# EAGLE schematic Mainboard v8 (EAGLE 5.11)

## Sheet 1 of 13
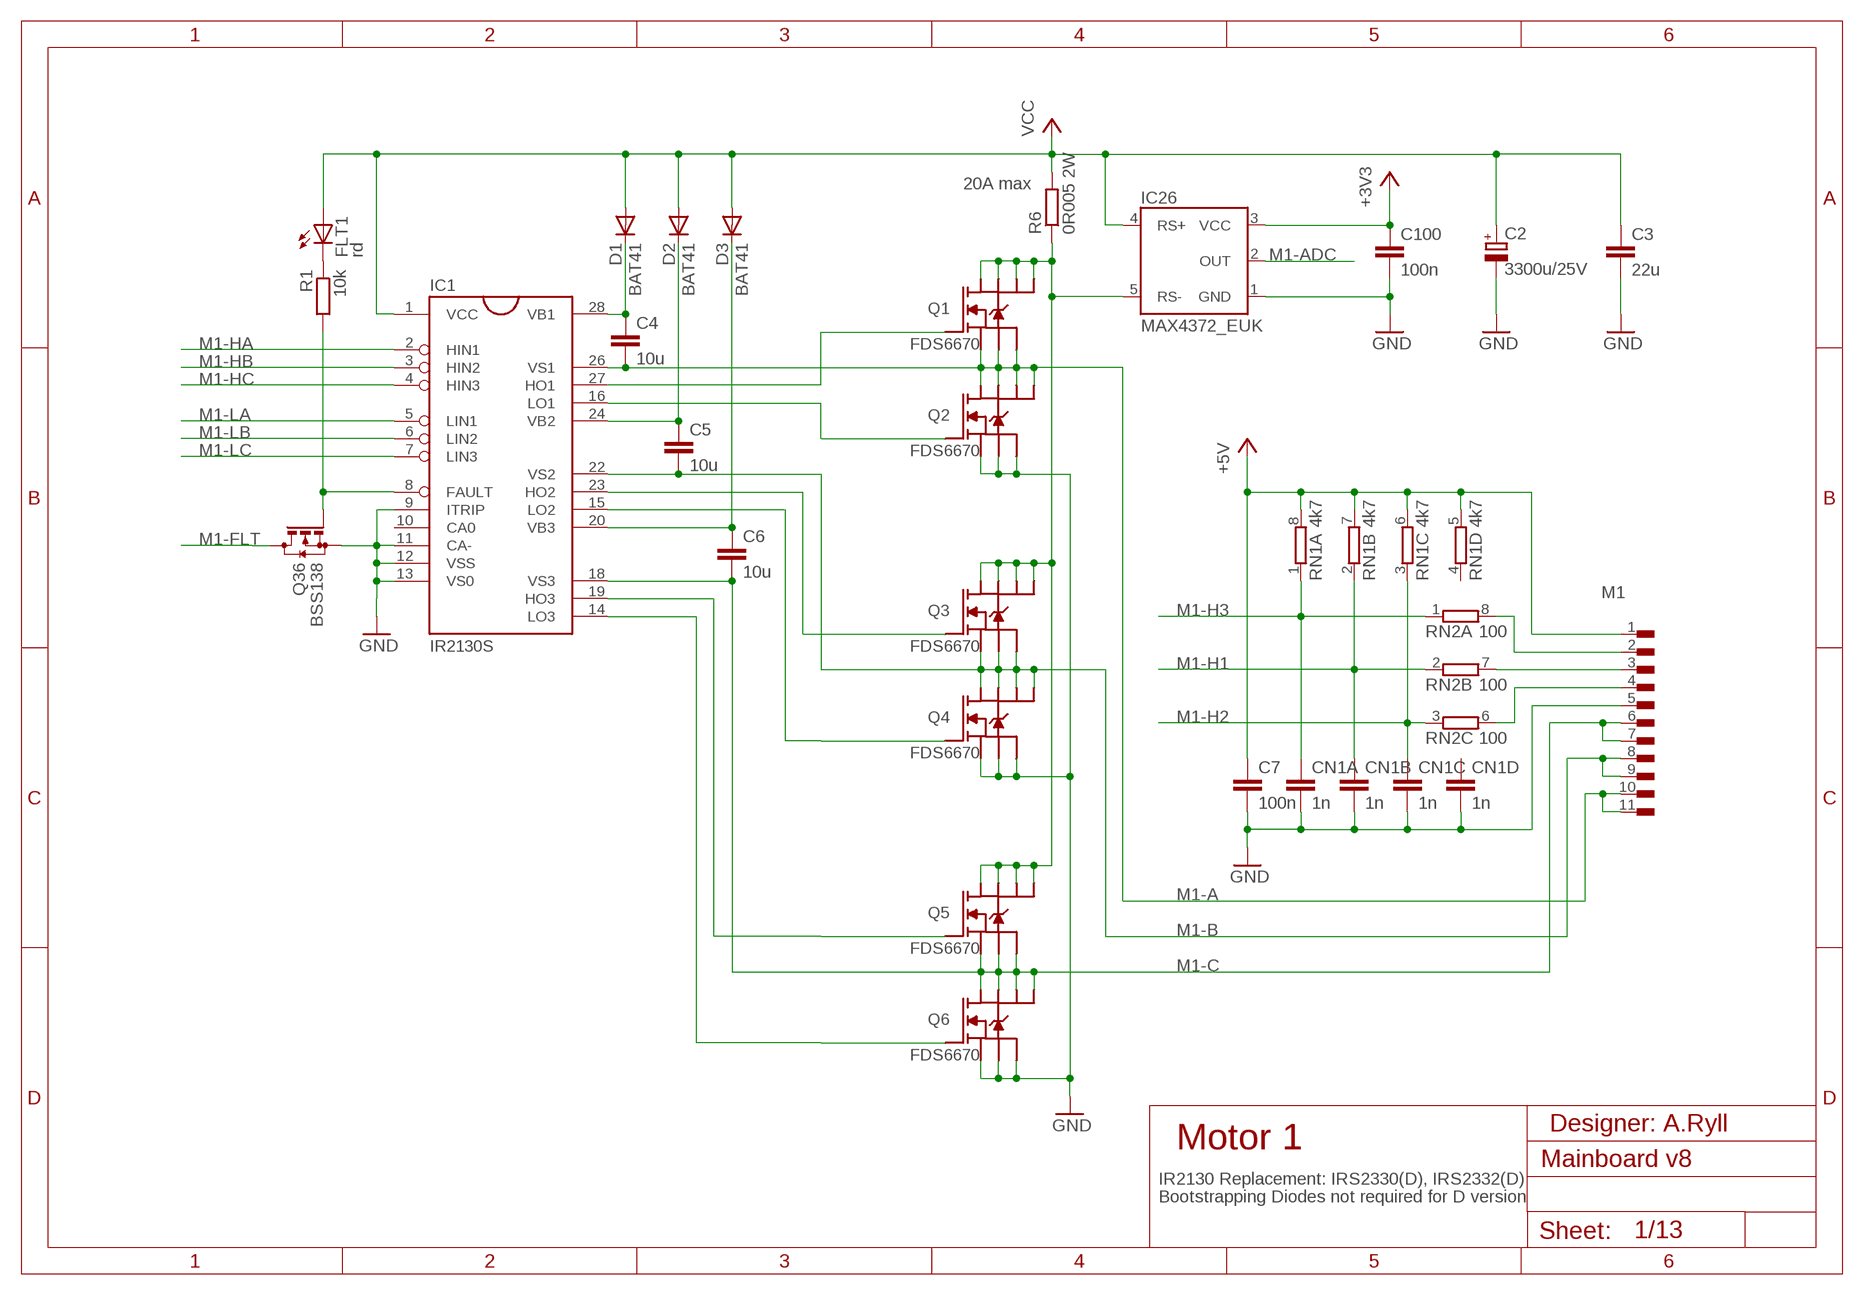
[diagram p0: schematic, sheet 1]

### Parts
C2  3300u/25V  CPOL-EU  [C25-16L]
C3  22u  C-EUC1206  [C1206]
C4  10u  C-EUC0805  [C0805]
C5  10u  C-EUC0805  [C0805]
C6  10u  C-EUC0805  [C0805]
C7  100n  C-EUC0805  [C0805]
C100  100n  C-EUC0805  [C0805]
CN1  1n  4C-NCAY16  [CAY16]
D1  BAT41  DIODE-SOD323-W  [SOD323-W]
D2  BAT41  DIODE-SOD323-W  [SOD323-W]
D3  BAT41  DIODE-SOD323-W  [SOD323-W]
FLT1  rd  LEDCHIP-LED0805  [CHIP-LED0805]
IC1  IR2130S  [SO28W]
IC26  MAX4372_EUK  [SOT23-5]
M1  MOLEX11  [MOLEX11]
Q1  FDS6670  NMOS4D  [SOIC8]
Q2  FDS6670  NMOS4D  [SOIC8]
Q3  FDS6670  NMOS4D  [SOIC8]
Q4  FDS6670  NMOS4D  [SOIC8]
Q5  FDS6670  NMOS4D  [SOIC8]
Q6  FDS6670  NMOS4D  [SOIC8]
Q36  BSS138  BSS123  [SOT23]
R1  10k  R-EU_R0805  [R0805]
R6  0R005 2W  R-EU_R2512  [R2512]
RN1  4k7  4R-NCAY16  [CAY16]
RN2  100  4R-NCAY16  [CAY16]

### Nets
+3V3: C100.1 IC26.3(VCC) ; also sheet 2,3,4,5,6,7,8,9,11,12,13
+5V: C7.1 M1.1(-1) RN1.5 RN1.6 RN1.7 RN1.8 ; also sheet 2,3,4,5,7,8,10,11
FLT1: IC1.8(FAULT) Q36.1(G) R1.2
GND: C2.B(-) C3.2 C7.2 C100.2 CN1.5 CN1.6 CN1.7 CN1.8 IC1.9(ITRIP) IC1.11(CA-) IC1.12(VSS) IC1.13(VS0) IC26.1(GND) M1.5(-5) Q2.1(S1) Q2.2(S2) Q2.3(S3) Q4.1(S1) Q4.2(S2) Q4.3(S3) Q6.1(S1) Q6.2(S2) Q6.3(S3) Q36.2(S) ; also sheet 2,3,4,5,6,7,8,9,10,11,12,13
M1-A: C4.2 IC1.26(VS1) M1.10(-10) M1.11(-11) Q1.1(S1) Q1.2(S2) Q1.3(S3) Q2.5(D1) Q2.6(D2) Q2.7(D3) Q2.8(D4)
M1-ADC: IC26.2(OUT) ; also sheet 6
M1-B: C5.2 IC1.22(VS2) M1.8(-8) M1.9(-9) Q3.1(S1) Q3.2(S2) Q3.3(S3) Q4.5(D1) Q4.6(D2) Q4.7(D3) Q4.8(D4)
M1-C: C6.2 IC1.18(VS3) M1.6(-6) M1.7(-7) Q5.1(S1) Q5.2(S2) Q5.3(S3) Q6.5(D1) Q6.6(D2) Q6.7(D3) Q6.8(D4)
M1-FLT: Q36.3(D) ; also sheet 6
M1-H1: CN1.2 RN1.2 RN2.2 ; also sheet 7,9
M1-H2: CN1.3 RN1.3 RN2.3 ; also sheet 7,9
M1-H3: CN1.1 RN1.1 RN2.1 ; also sheet 7,9
M1-HA: IC1.2(HIN1) ; also sheet 9
M1-HB: IC1.3(HIN2) ; also sheet 9
M1-HC: IC1.4(HIN3) ; also sheet 9
M1-LA: IC1.5(LIN1) ; also sheet 9
M1-LB: IC1.6(LIN2) ; also sheet 9
M1-LC: IC1.7(LIN3) ; also sheet 9
M1-PWR: IC26.5(RS-) Q1.5(D1) Q1.6(D2) Q1.7(D3) Q1.8(D4) Q3.5(D1) Q3.6(D2) Q3.7(D3) Q3.8(D4) Q5.5(D1) Q5.6(D2) Q5.7(D3) Q5.8(D4) R6.1
N$2: IC1.27(HO1) Q1.4(G)
N$4: IC1.16(LO1) Q2.4(G)
N$5: IC1.23(HO2) Q3.4(G)
N$8: M1.2(-2) RN2.8
N$9: M1.3(-3) RN2.7
N$10: M1.4(-4) RN2.6
N$12: IC1.15(LO2) Q4.4(G)
N$16: IC1.19(HO3) Q5.4(G)
N$18: IC1.14(LO3) Q6.4(G)
N$33: C4.1 D1.C IC1.28(VB1)
N$35: C5.1 D2.C IC1.24(VB2)
N$37: C6.1 D3.C IC1.20(VB3)
N$51: FLT1.C R1.1
VCC: C2.A(+) C3.1 D1.A D2.A D3.A FLT1.A IC1.1(VCC) IC26.4(RS+) R6.2 ; also sheet 2,3,4,5,8,10
Unconnected: CN1.4 IC1.10(CA0) RN1.4 RN2.4 RN2.5

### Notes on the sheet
- 20A max
- Designer: A.Ryll
- Motor 1
- IR2130 Replacement: IRS2330(D), IRS2332(D)
- Bootstrapping Diodes not required for D version

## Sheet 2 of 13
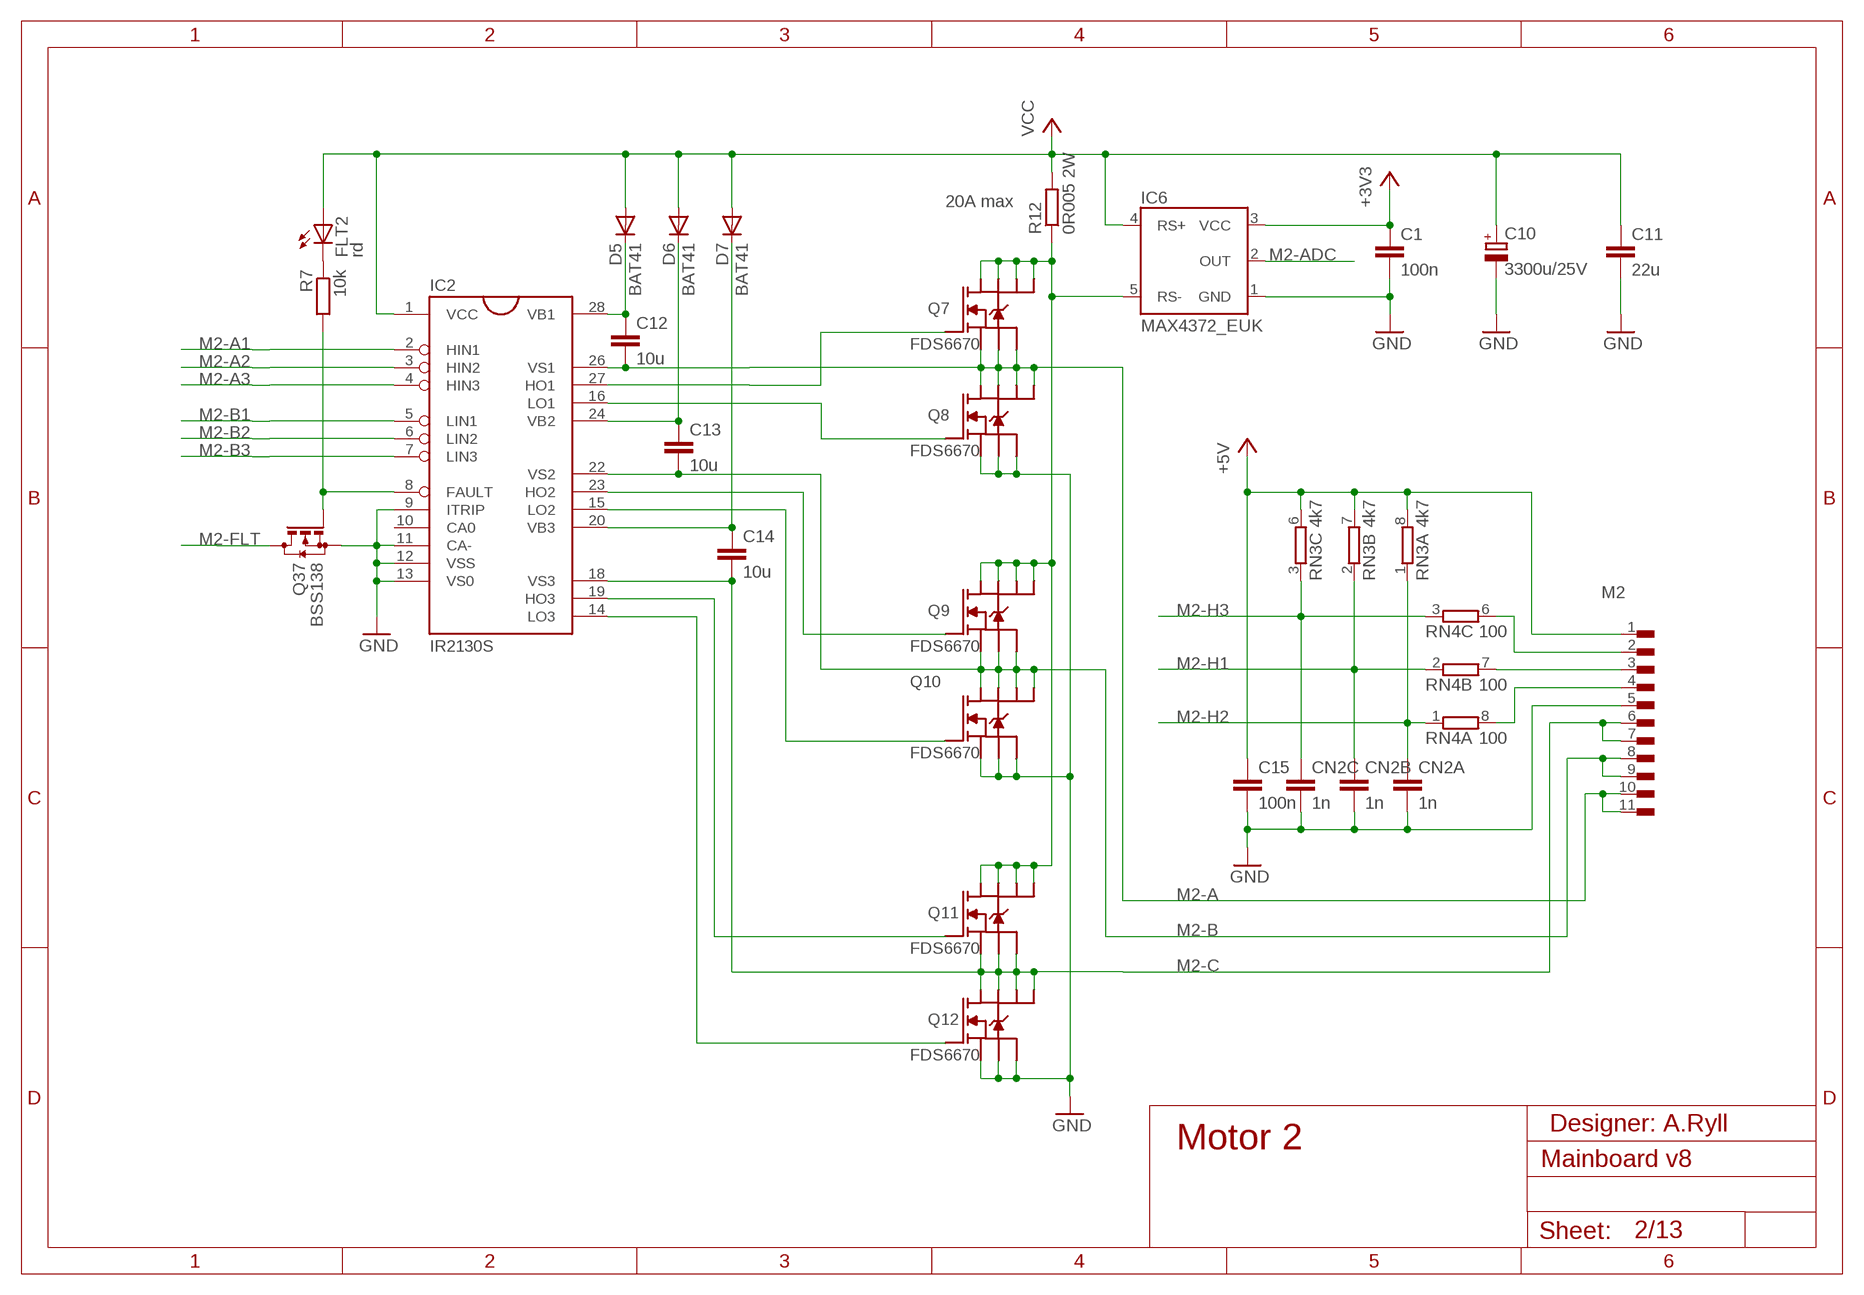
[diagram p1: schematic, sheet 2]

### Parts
C1  100n  C-EUC0805  [C0805]
C10  3300u/25V  CPOL-EU  [C25-16L]
C11  22u  C-EUC1206  [C1206]
C12  10u  C-EUC0805  [C0805]
C13  10u  C-EUC0805  [C0805]
C14  10u  C-EUC0805  [C0805]
C15  100n  C-EUC0805  [C0805]
CN2  1n  4C-NCAY16  [CAY16]
D5  BAT41  DIODE-SOD323-W  [SOD323-W]
D6  BAT41  DIODE-SOD323-W  [SOD323-W]
D7  BAT41  DIODE-SOD323-W  [SOD323-W]
FLT2  rd  LEDCHIP-LED0805  [CHIP-LED0805]
IC2  IR2130S  [SO28W]
IC6  MAX4372_EUK  [SOT23-5]
M2  MOLEX11  [MOLEX11]
Q7  FDS6670  NMOS4D  [SOIC8]
Q8  FDS6670  NMOS4D  [SOIC8]
Q9  FDS6670  NMOS4D  [SOIC8]
Q10  FDS6670  NMOS4D  [SOIC8]
Q11  FDS6670  NMOS4D  [SOIC8]
Q12  FDS6670  NMOS4D  [SOIC8]
Q37  BSS138  BSS123  [SOT23]
R7  10k  R-EU_R0805  [R0805]
R12  0R005 2W  R-EU_R2512  [R2512]
RN3  4k7  4R-NCAY16  [CAY16]
RN4  100  4R-NCAY16  [CAY16]

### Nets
+3V3: C1.1 IC6.3(VCC) ; also sheet 1,3,4,5,6,7,8,9,11,12,13
+5V: C15.1 M2.1(-1) RN3.6 RN3.7 RN3.8 ; also sheet 1,3,4,5,7,8,10,11
FLT2: IC2.8(FAULT) Q37.1(G) R7.2
GND: C1.2 C10.B(-) C11.2 C15.2 CN2.6 CN2.7 CN2.8 IC2.9(ITRIP) IC2.11(CA-) IC2.12(VSS) IC2.13(VS0) IC6.1(GND) M2.5(-5) Q8.1(S1) Q8.2(S2) Q8.3(S3) Q10.1(S1) Q10.2(S2) Q10.3(S3) Q12.1(S1) Q12.2(S2) Q12.3(S3) Q37.2(S) ; also sheet 1,3,4,5,6,7,8,9,10,11,12,13
M2-A: C12.2 IC2.26(VS1) M2.10(-10) M2.11(-11) Q7.1(S1) Q7.2(S2) Q7.3(S3) Q8.5(D1) Q8.6(D2) Q8.7(D3) Q8.8(D4)
M2-A1: IC2.2(HIN1) ; also sheet 9
M2-A2: IC2.3(HIN2) ; also sheet 9
M2-A3: IC2.4(HIN3) ; also sheet 9
M2-ADC: IC6.2(OUT) ; also sheet 6
M2-B: C13.2 IC2.22(VS2) M2.8(-8) M2.9(-9) Q9.1(S1) Q9.2(S2) Q9.3(S3) Q10.5(D1) Q10.6(D2) Q10.7(D3) Q10.8(D4)
M2-B1: IC2.5(LIN1) ; also sheet 9
M2-B2: IC2.6(LIN2) ; also sheet 9
M2-B3: IC2.7(LIN3) ; also sheet 9
M2-C: C14.2 IC2.18(VS3) M2.6(-6) M2.7(-7) Q11.1(S1) Q11.2(S2) Q11.3(S3) Q12.5(D1) Q12.6(D2) Q12.7(D3) Q12.8(D4)
M2-FLT: Q37.3(D) ; also sheet 6
M2-H1: CN2.2 RN3.2 RN4.2 ; also sheet 7,9
M2-H2: CN2.1 RN3.1 RN4.1 ; also sheet 7,9
M2-H3: CN2.3 RN3.3 RN4.3 ; also sheet 7,9
M2-PWR: IC6.5(RS-) Q7.5(D1) Q7.6(D2) Q7.7(D3) Q7.8(D4) Q9.5(D1) Q9.6(D2) Q9.7(D3) Q9.8(D4) Q11.5(D1) Q11.6(D2) Q11.7(D3) Q11.8(D4) R12.1
N$34: IC2.23(HO2) Q9.4(G)
N$36: IC2.15(LO2) Q10.4(G)
N$38: IC2.19(HO3) Q11.4(G)
N$40: IC2.14(LO3) Q12.4(G)
N$41: C12.1 D5.C IC2.28(VB1)
N$42: C13.1 D6.C IC2.24(VB2)
N$43: C14.1 D7.C IC2.20(VB3)
N$44: IC2.16(LO1) Q8.4(G)
N$48: FLT2.C R7.1
N$49: IC2.27(HO1) Q7.4(G)
N$124: M2.2(-2) RN4.6
N$127: M2.4(-4) RN4.8
N$148: M2.3(-3) RN4.7
VCC: C10.A(+) C11.1 D5.A D6.A D7.A FLT2.A IC2.1(VCC) IC6.4(RS+) R12.2 ; also sheet 1,3,4,5,8,10
Unconnected: CN2.4 CN2.5 IC2.10(CA0) RN3.4 RN3.5 RN4.4 RN4.5

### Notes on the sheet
- 20A max
- Designer: A.Ryll
- Motor 2

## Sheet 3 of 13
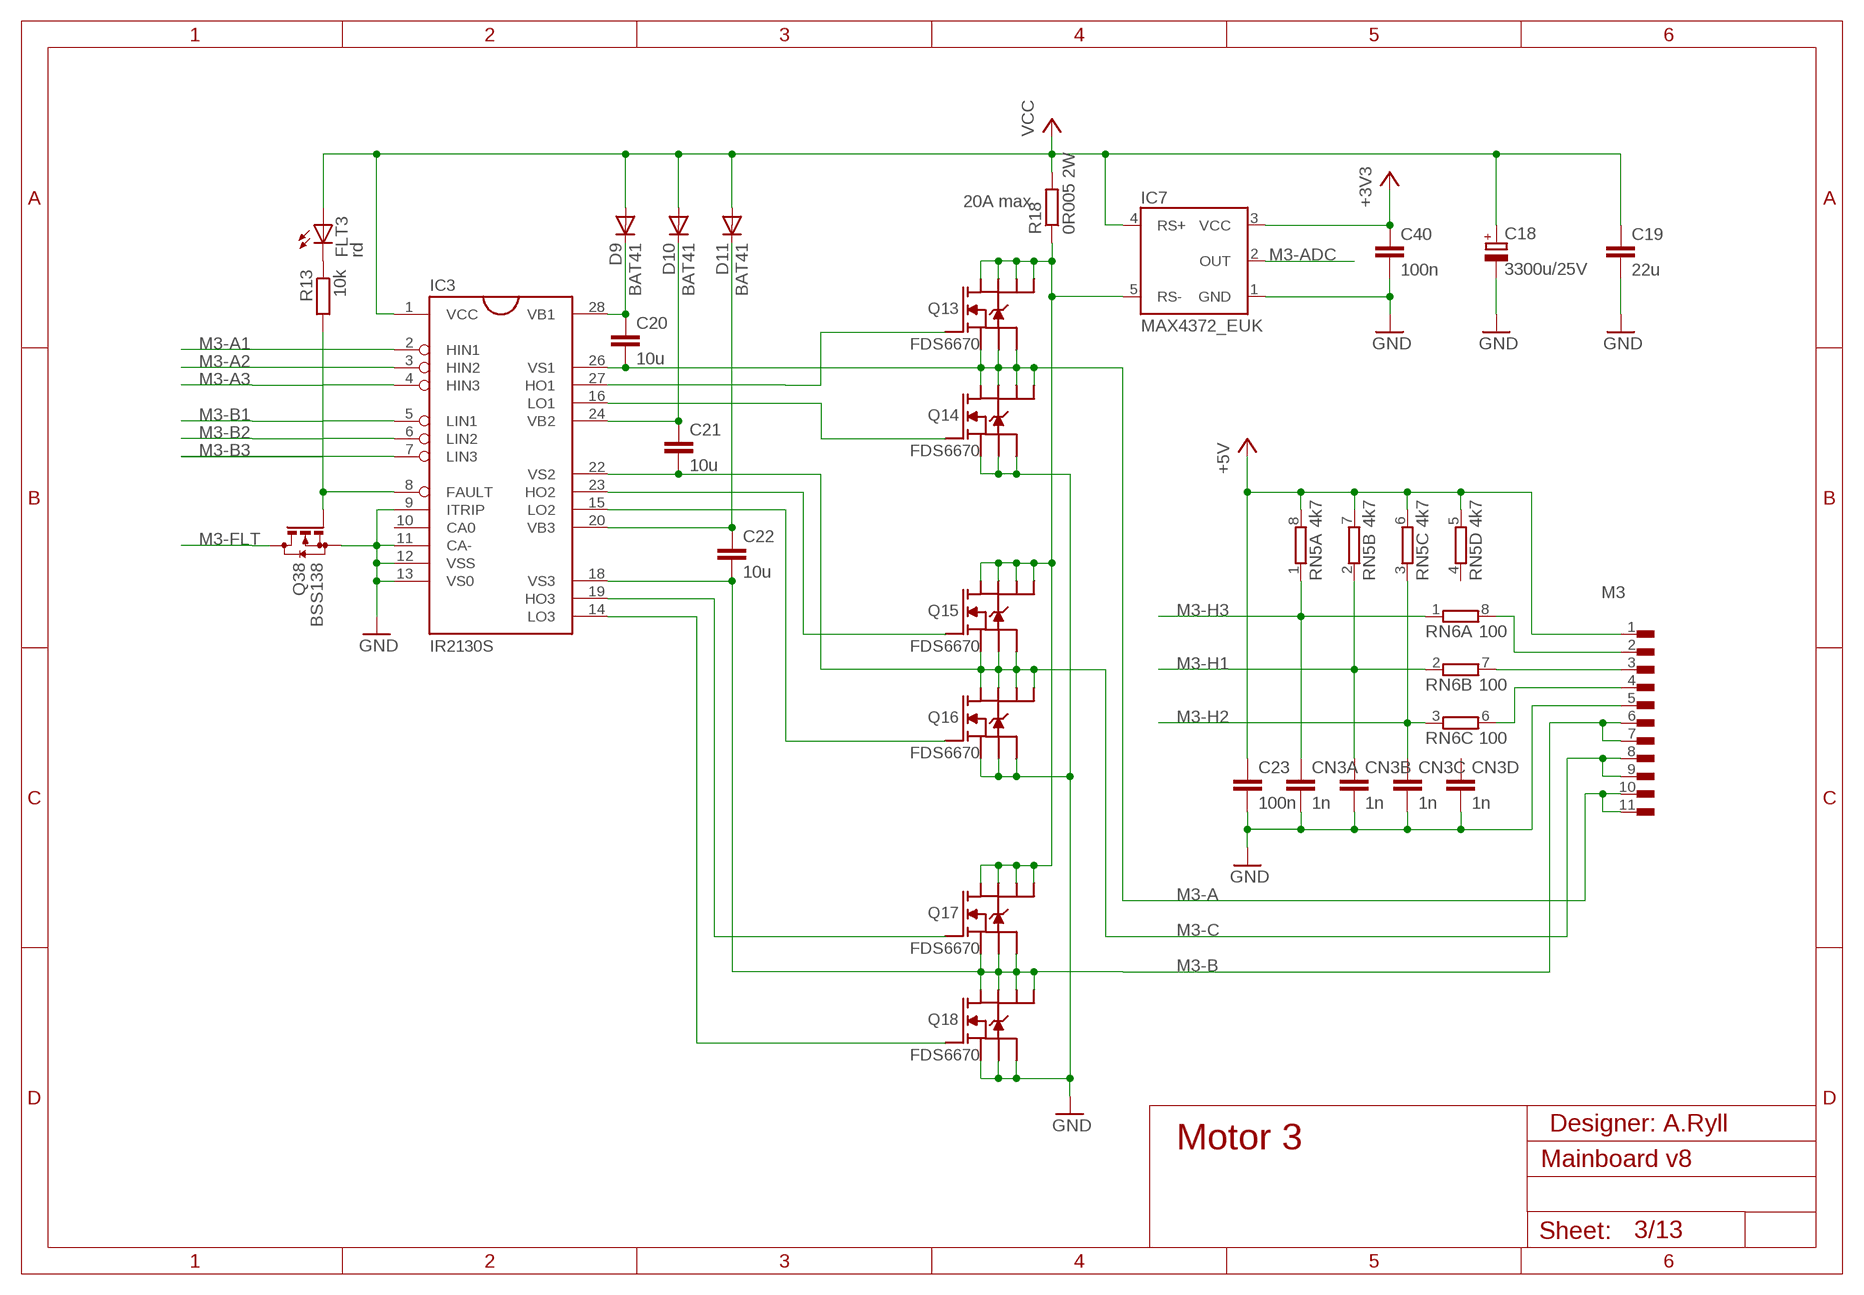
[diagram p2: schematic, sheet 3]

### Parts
C18  3300u/25V  CPOL-EU  [C25-16L]
C19  22u  C-EUC1206  [C1206]
C20  10u  C-EUC0805  [C0805]
C21  10u  C-EUC0805  [C0805]
C22  10u  C-EUC0805  [C0805]
C23  100n  C-EUC0805  [C0805]
C40  100n  C-EUC0805  [C0805]
CN3  1n  4C-NCAY16  [CAY16]
D9  BAT41  DIODE-SOD323-W  [SOD323-W]
D10  BAT41  DIODE-SOD323-W  [SOD323-W]
D11  BAT41  DIODE-SOD323-W  [SOD323-W]
FLT3  rd  LEDCHIP-LED0805  [CHIP-LED0805]
IC3  IR2130S  [SO28W]
IC7  MAX4372_EUK  [SOT23-5]
M3  MOLEX11  [MOLEX11]
Q13  FDS6670  NMOS4D  [SOIC8]
Q14  FDS6670  NMOS4D  [SOIC8]
Q15  FDS6670  NMOS4D  [SOIC8]
Q16  FDS6670  NMOS4D  [SOIC8]
Q17  FDS6670  NMOS4D  [SOIC8]
Q18  FDS6670  NMOS4D  [SOIC8]
Q38  BSS138  BSS123  [SOT23]
R13  10k  R-EU_R0805  [R0805]
R18  0R005 2W  R-EU_R2512  [R2512]
RN5  4k7  4R-NCAY16  [CAY16]
RN6  100  4R-NCAY16  [CAY16]

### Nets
+3V3: C40.1 IC7.3(VCC) ; also sheet 1,2,4,5,6,7,8,9,11,12,13
+5V: C23.1 M3.1(-1) RN5.5 RN5.6 RN5.7 RN5.8 ; also sheet 1,2,4,5,7,8,10,11
FLT3: IC3.8(FAULT) Q38.1(G) R13.2
GND: C18.B(-) C19.2 C23.2 C40.2 CN3.5 CN3.6 CN3.7 CN3.8 IC3.9(ITRIP) IC3.11(CA-) IC3.12(VSS) IC3.13(VS0) IC7.1(GND) M3.5(-5) Q14.1(S1) Q14.2(S2) Q14.3(S3) Q16.1(S1) Q16.2(S2) Q16.3(S3) Q18.1(S1) Q18.2(S2) Q18.3(S3) Q38.2(S) ; also sheet 1,2,4,5,6,7,8,9,10,11,12,13
M3-A: C20.2 IC3.26(VS1) M3.10(-10) M3.11(-11) Q13.1(S1) Q13.2(S2) Q13.3(S3) Q14.5(D1) Q14.6(D2) Q14.7(D3) Q14.8(D4)
M3-A1: IC3.2(HIN1) ; also sheet 9
M3-A2: IC3.3(HIN2) ; also sheet 9
M3-A3: IC3.4(HIN3) ; also sheet 9
M3-ADC: IC7.2(OUT) ; also sheet 6
M3-B: C21.2 IC3.22(VS2) M3.8(-8) M3.9(-9) Q15.1(S1) Q15.2(S2) Q15.3(S3) Q16.5(D1) Q16.6(D2) Q16.7(D3) Q16.8(D4)
M3-B1: IC3.5(LIN1) ; also sheet 9
M3-B2: IC3.6(LIN2) ; also sheet 9
M3-B3: IC3.7(LIN3) ; also sheet 9
M3-C: C22.2 IC3.18(VS3) M3.6(-6) M3.7(-7) Q17.1(S1) Q17.2(S2) Q17.3(S3) Q18.5(D1) Q18.6(D2) Q18.7(D3) Q18.8(D4)
M3-FLT: Q38.3(D) ; also sheet 6
M3-H1: CN3.2 RN5.2 RN6.2 ; also sheet 7,9
M3-H2: CN3.3 RN5.3 RN6.3 ; also sheet 7,9
M3-H3: CN3.1 RN5.1 RN6.1 ; also sheet 7,9
N$1: IC7.5(RS-) Q13.5(D1) Q13.6(D2) Q13.7(D3) Q13.8(D4) Q15.5(D1) Q15.6(D2) Q15.7(D3) Q15.8(D4) Q17.5(D1) Q17.6(D2) Q17.7(D3) Q17.8(D4) R18.1
N$53: IC3.23(HO2) Q15.4(G)
N$54: IC3.15(LO2) Q16.4(G)
N$55: IC3.19(HO3) Q17.4(G)
N$56: IC3.14(LO3) Q18.4(G)
N$57: C20.1 D9.C IC3.28(VB1)
N$58: C21.1 D10.C IC3.24(VB2)
N$59: C22.1 D11.C IC3.20(VB3)
N$60: IC3.16(LO1) Q14.4(G)
N$63: FLT3.C R13.1
N$64: IC3.27(HO1) Q13.4(G)
N$216: M3.2(-2) RN6.8
N$217: M3.4(-4) RN6.6
N$222: M3.3(-3) RN6.7
VCC: C18.A(+) C19.1 D9.A D10.A D11.A FLT3.A IC3.1(VCC) IC7.4(RS+) R18.2 ; also sheet 1,2,4,5,8,10
Unconnected: CN3.4 IC3.10(CA0) RN5.4 RN6.4 RN6.5

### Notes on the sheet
- 20A max
- Designer: A.Ryll
- Motor 3

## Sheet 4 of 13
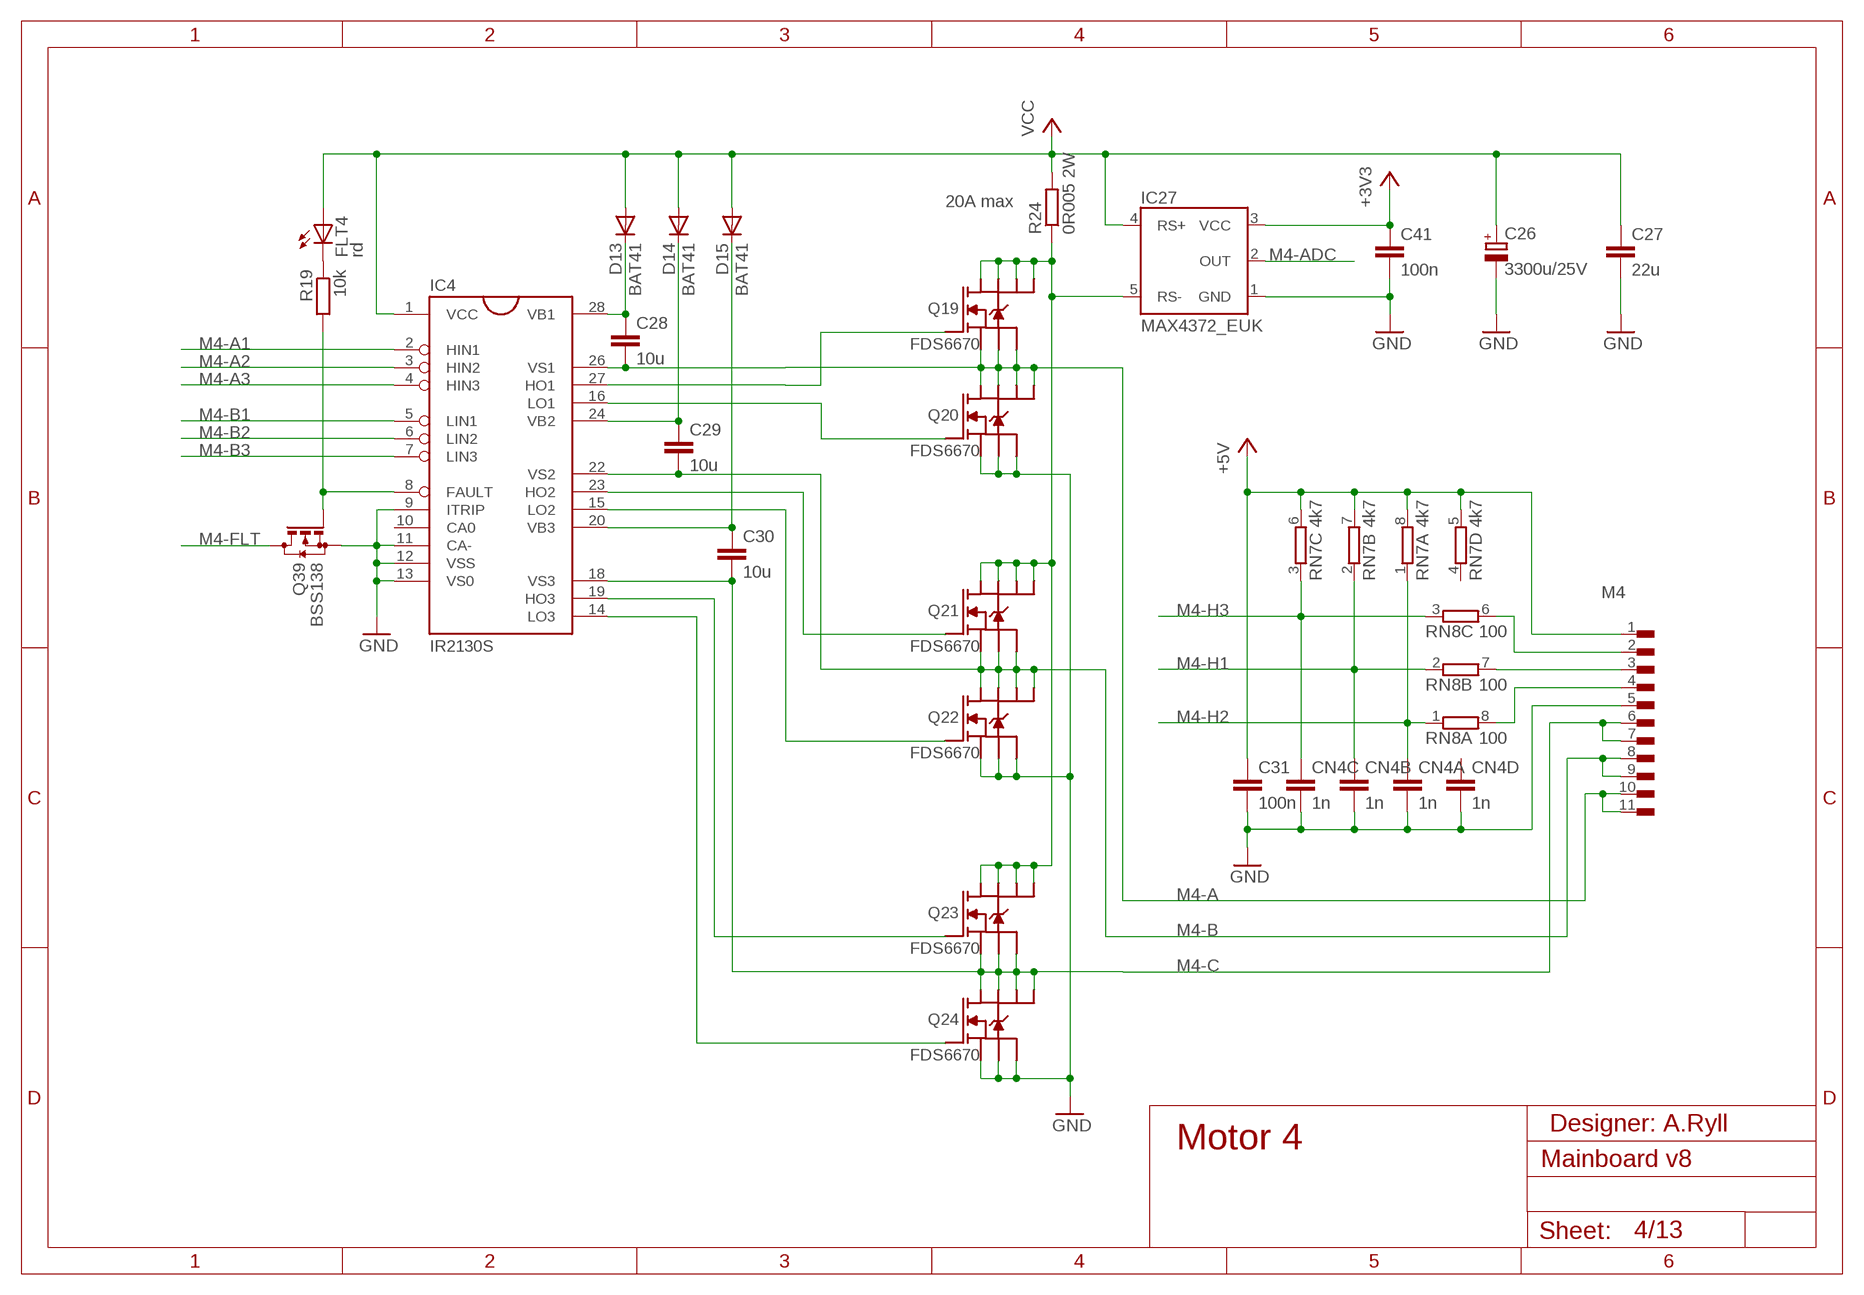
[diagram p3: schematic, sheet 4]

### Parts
C26  3300u/25V  CPOL-EUI  [C25-16L]
C27  22u  C-EUC1206  [C1206]
C28  10u  C-EUC0805  [C0805]
C29  10u  C-EUC0805  [C0805]
C30  10u  C-EUC0805  [C0805]
C31  100n  C-EUC0805  [C0805]
C41  100n  C-EUC0805  [C0805]
CN4  1n  4C-NCAY16  [CAY16]
D13  BAT41  DIODE-SOD323-W  [SOD323-W]
D14  BAT41  DIODE-SOD323-W  [SOD323-W]
D15  BAT41  DIODE-SOD323-W  [SOD323-W]
FLT4  rd  LEDCHIP-LED0805  [CHIP-LED0805]
IC4  IR2130S  [SO28W]
IC27  MAX4372_EUK  [SOT23-5]
M4  MOLEX11  [MOLEX11]
Q19  FDS6670  NMOS4D  [SOIC8]
Q20  FDS6670  NMOS4D  [SOIC8]
Q21  FDS6670  NMOS4D  [SOIC8]
Q22  FDS6670  NMOS4D  [SOIC8]
Q23  FDS6670  NMOS4D  [SOIC8]
Q24  FDS6670  NMOS4D  [SOIC8]
Q39  BSS138  BSS123  [SOT23]
R19  10k  R-EU_R0805  [R0805]
R24  0R005 2W  R-EU_R2512  [R2512]
RN7  4k7  4R-NCAY16  [CAY16]
RN8  100  4R-NCAY16  [CAY16]

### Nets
+3V3: C41.1 IC27.3(VCC) ; also sheet 1,2,3,5,6,7,8,9,11,12,13
+5V: C31.1 M4.1(-1) RN7.5 RN7.6 RN7.7 RN7.8 ; also sheet 1,2,3,5,7,8,10,11
FLT4: IC4.8(FAULT) Q39.1(G) R19.2
GND: C26.A(-) C27.2 C31.2 C41.2 CN4.5 CN4.6 CN4.7 CN4.8 IC4.9(ITRIP) IC4.11(CA-) IC4.12(VSS) IC4.13(VS0) IC27.1(GND) M4.5(-5) Q20.1(S1) Q20.2(S2) Q20.3(S3) Q22.1(S1) Q22.2(S2) Q22.3(S3) Q24.1(S1) Q24.2(S2) Q24.3(S3) Q39.2(S) ; also sheet 1,2,3,5,6,7,8,9,10,11,12,13
M4-A: C28.2 IC4.26(VS1) M4.10(-10) M4.11(-11) Q19.1(S1) Q19.2(S2) Q19.3(S3) Q20.5(D1) Q20.6(D2) Q20.7(D3) Q20.8(D4)
M4-A1: IC4.2(HIN1) ; also sheet 9
M4-A2: IC4.3(HIN2) ; also sheet 9
M4-A3: IC4.4(HIN3) ; also sheet 9
M4-ADC: IC27.2(OUT) ; also sheet 6
M4-B: C29.2 IC4.22(VS2) M4.8(-8) M4.9(-9) Q21.1(S1) Q21.2(S2) Q21.3(S3) Q22.5(D1) Q22.6(D2) Q22.7(D3) Q22.8(D4)
M4-B1: IC4.5(LIN1) ; also sheet 9
M4-B2: IC4.6(LIN2) ; also sheet 9
M4-B3: IC4.7(LIN3) ; also sheet 9
M4-C: C30.2 IC4.18(VS3) M4.6(-6) M4.7(-7) Q23.1(S1) Q23.2(S2) Q23.3(S3) Q24.5(D1) Q24.6(D2) Q24.7(D3) Q24.8(D4)
M4-FLT: Q39.3(D) ; also sheet 6
M4-H1: CN4.2 RN7.2 RN8.2 ; also sheet 7,9
M4-H2: CN4.1 RN7.1 RN8.1 ; also sheet 7,9
M4-H3: CN4.3 RN7.3 RN8.3 ; also sheet 7,9
M4-PWR: IC27.5(RS-) Q19.5(D1) Q19.6(D2) Q19.7(D3) Q19.8(D4) Q21.5(D1) Q21.6(D2) Q21.7(D3) Q21.8(D4) Q23.5(D1) Q23.6(D2) Q23.7(D3) Q23.8(D4) R24.1
N$66: IC4.23(HO2) Q21.4(G)
N$67: IC4.15(LO2) Q22.4(G)
N$68: IC4.19(HO3) Q23.4(G)
N$69: IC4.14(LO3) Q24.4(G)
N$70: C28.1 D13.C IC4.28(VB1)
N$71: C29.1 D14.C IC4.24(VB2)
N$72: C30.1 D15.C IC4.20(VB3)
N$73: IC4.16(LO1) Q20.4(G)
N$80: FLT4.C R19.1
N$83: IC4.27(HO1) Q19.4(G)
N$237: M4.2(-2) RN8.6
N$238: M4.4(-4) RN8.8
N$243: M4.3(-3) RN8.7
VCC: C26.B(+) C27.1 D13.A D14.A D15.A FLT4.A IC4.1(VCC) IC27.4(RS+) R24.2 ; also sheet 1,2,3,5,8,10
Unconnected: CN4.4 IC4.10(CA0) RN7.4 RN8.4 RN8.5

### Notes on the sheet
- 20A max
- Designer: A.Ryll
- Motor 4

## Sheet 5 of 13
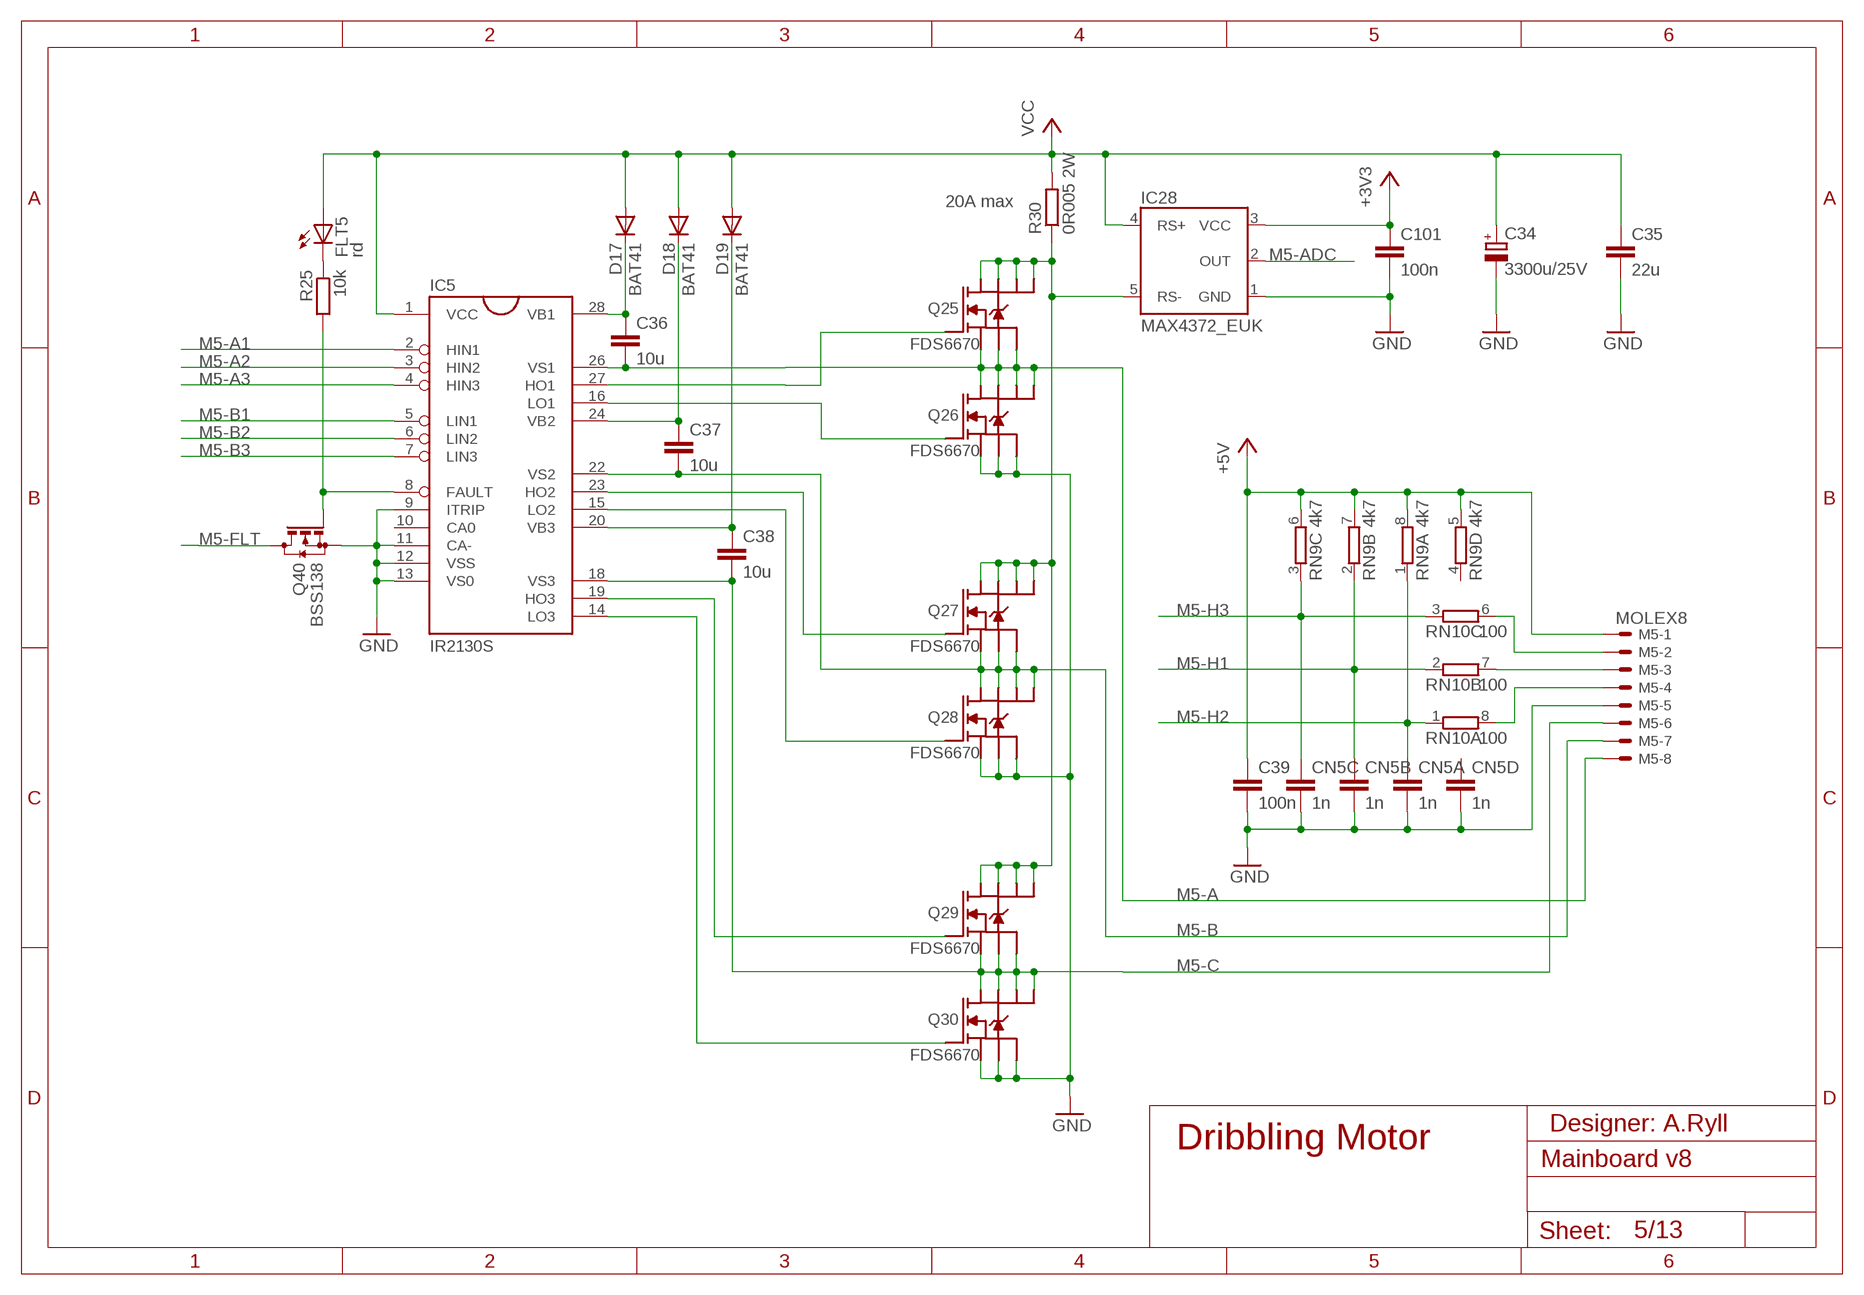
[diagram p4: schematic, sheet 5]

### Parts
C34  3300u/25V  CPOL-EUI  [C25-16L]
C35  22u  C-EUC1206  [C1206]
C36  10u  C-EUC0805  [C0805]
C37  10u  C-EUC0805  [C0805]
C38  10u  C-EUC0805  [C0805]
C39  100n  C-EUC0805  [C0805]
C101  100n  C-EUC0805  [C0805]
CN5  1n  4C-NCAY16  [CAY16]
D17  BAT41  DIODE-SOD323-W  [SOD323-W]
D18  BAT41  DIODE-SOD323-W  [SOD323-W]
D19  BAT41  DIODE-SOD323-W  [SOD323-W]
FLT5  rd  LEDCHIP-LED0805  [CHIP-LED0805]
IC5  IR2130S  [SO28W]
IC28  MAX4372_EUK  [SOT23-5]
M5  MOLEX8  22-27-2081-08  [6410-08]
Q25  FDS6670  NMOS4D  [SOIC8]
Q26  FDS6670  NMOS4D  [SOIC8]
Q27  FDS6670  NMOS4D  [SOIC8]
Q28  FDS6670  NMOS4D  [SOIC8]
Q29  FDS6670  NMOS4D  [SOIC8]
Q30  FDS6670  NMOS4D  [SOIC8]
Q40  BSS138  BSS123  [SOT23]
R25  10k  R-EU_R0805  [R0805]
R30  0R005 2W  R-EU_R2512  [R2512]
RN9  4k7  4R-NCAY16  [CAY16]
RN10  100  4R-NCAY16  [CAY16]

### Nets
+3V3: C101.1 IC28.3(VCC) ; also sheet 1,2,3,4,6,7,8,9,11,12,13
+5V: C39.1 M5.1 RN9.5 RN9.6 RN9.7 RN9.8 ; also sheet 1,2,3,4,7,8,10,11
FLT5: IC5.8(FAULT) Q40.1(G) R25.2
GND: C34.A(-) C35.2 C39.2 C101.2 CN5.5 CN5.6 CN5.7 CN5.8 IC5.9(ITRIP) IC5.11(CA-) IC5.12(VSS) IC5.13(VS0) IC28.1(GND) M5.5 Q26.1(S1) Q26.2(S2) Q26.3(S3) Q28.1(S1) Q28.2(S2) Q28.3(S3) Q30.1(S1) Q30.2(S2) Q30.3(S3) Q40.2(S) ; also sheet 1,2,3,4,6,7,8,9,10,11,12,13
M5-A: C36.2 IC5.26(VS1) M5.8 Q25.1(S1) Q25.2(S2) Q25.3(S3) Q26.5(D1) Q26.6(D2) Q26.7(D3) Q26.8(D4)
M5-A1: IC5.2(HIN1) ; also sheet 9
M5-A2: IC5.3(HIN2) ; also sheet 9
M5-A3: IC5.4(HIN3) ; also sheet 9
M5-ADC: IC28.2(OUT) ; also sheet 6
M5-B: C37.2 IC5.22(VS2) M5.7 Q27.1(S1) Q27.2(S2) Q27.3(S3) Q28.5(D1) Q28.6(D2) Q28.7(D3) Q28.8(D4)
M5-B1: IC5.5(LIN1) ; also sheet 9
M5-B2: IC5.6(LIN2) ; also sheet 9
M5-B3: IC5.7(LIN3) ; also sheet 9
M5-C: C38.2 IC5.18(VS3) M5.6 Q29.1(S1) Q29.2(S2) Q29.3(S3) Q30.5(D1) Q30.6(D2) Q30.7(D3) Q30.8(D4)
M5-FLT: Q40.3(D) ; also sheet 6
M5-H1: CN5.2 RN9.2 RN10.2 ; also sheet 7,9
M5-H2: CN5.1 RN9.1 RN10.1 ; also sheet 7,9
M5-H3: CN5.3 RN9.3 RN10.3 ; also sheet 7,9
M5-PWR: IC28.5(RS-) Q25.5(D1) Q25.6(D2) Q25.7(D3) Q25.8(D4) Q27.5(D1) Q27.6(D2) Q27.7(D3) Q27.8(D4) Q29.5(D1) Q29.6(D2) Q29.7(D3) Q29.8(D4) R30.1
N$89: IC5.23(HO2) Q27.4(G)
N$92: IC5.15(LO2) Q28.4(G)
N$93: IC5.19(HO3) Q29.4(G)
N$95: IC5.14(LO3) Q30.4(G)
N$96: C36.1 D17.C IC5.28(VB1)
N$97: C37.1 D18.C IC5.24(VB2)
N$99: C38.1 D19.C IC5.20(VB3)
N$147: IC5.16(LO1) Q26.4(G)
N$158: FLT5.C R25.1
N$162: IC5.27(HO1) Q25.4(G)
N$258: M5.2 RN10.6
N$259: M5.4 RN10.8
N$264: M5.3 RN10.7
VCC: C34.B(+) C35.1 D17.A D18.A D19.A FLT5.A IC5.1(VCC) IC28.4(RS+) R30.2 ; also sheet 1,2,3,4,8,10
Unconnected: CN5.4 IC5.10(CA0) RN9.4 RN10.4 RN10.5

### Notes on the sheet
- 20A max
- Designer: A.Ryll
- Dribbling Motor

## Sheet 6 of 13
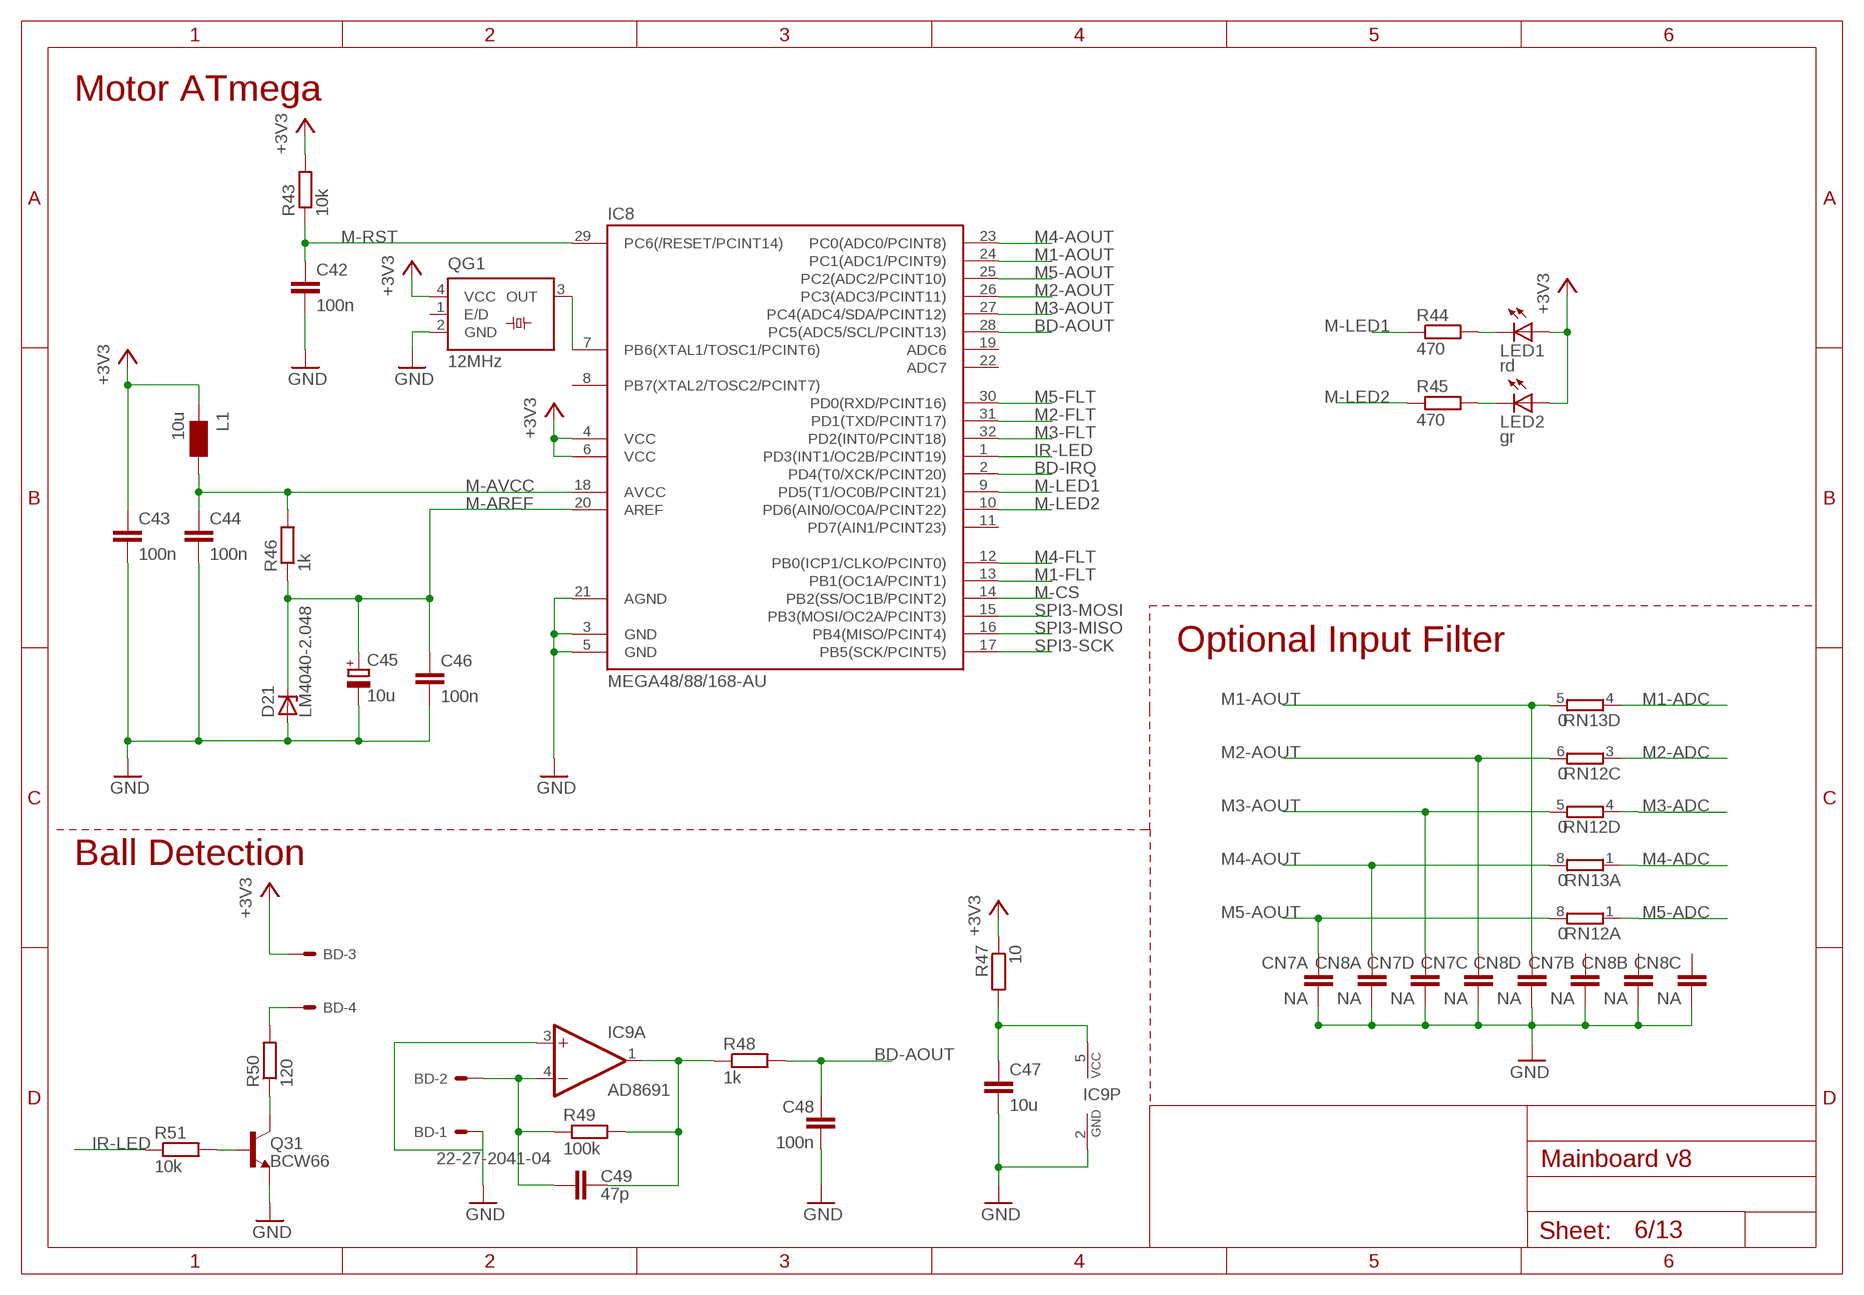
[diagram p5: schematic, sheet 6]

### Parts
BD  22-27-2041-04  [6410-04]
C42  100n  C-EUC0805  [C0805]
C43  100n  C-EUC0805  [C0805]
C44  100n  C-EUC0805  [C0805]
C45  10u  CPOL-EUC/6032-28W  [C/6032-28W]
C46  100n  C-EUC0805  [C0805]
C47  10u  C-EUC0805  [C0805]
C48  100n  C-EUC0805  [C0805]
C49  47p  C-EUC0805  [C0805]
CN7  NA  4C-NCAY16  [CAY16]
CN8  NA  4C-NCAY16  [CAY16]
D21  LM4040-2.048  ZENER-DIODELM4040  [SOT23]
IC8  MEGA48/88/168-AU  [TQFP32-08]
IC9  AD8691  AD-OP1RT  [SOT23-5]
L1  10u  WE-MI_0805  [0805]
LED1  rd  LEDCHIP-LED0805  [CHIP-LED0805]
LED2  gr  LEDCHIP-LED0805  [CHIP-LED0805]
Q31  BCW66  BCW60SMD  [SOT23-BEC]
QG1  12MHz  SM77H  [SM77H]
R43  10k  R-EU_R0805  [R0805]
R44  470  R-EU_R0805  [R0805]
R45  470  R-EU_R0805  [R0805]
R46  1k  R-EU_R0805  [R0805]
R47  10  R-EU_R0805  [R0805]
R48  1k  R-EU_R0805  [R0805]
R49  100k  R-EU_R0805  [R0805]
R50  120  R-EU_R0805  [R0805]
R51  10k  R-EU_R0805  [R0805]
RN12  0  4R-NCAY16  [CAY16]
RN13  0  4R-NCAY16  [CAY16]

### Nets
+3V3: BD.3 C43.1 IC8.4(VCC) IC8.6(VCC) L1.1 LED1.A LED2.A QG1.4(VCC) R43.2 R47.1 ; also sheet 1,2,3,4,5,7,8,9,11,12,13
BD-AOUT: C48.2 IC8.28(PC5(ADC5/SCL/PCINT13)) R48.2
BD-IRQ: IC8.2(PD4(T0/XCK/PCINT20)) ; also sheet 9
GND: BD.1 C42.2 C43.2 C44.2 C45.- C46.2 C47.2 C48.1 CN7.5 CN7.6 CN7.7 CN7.8 CN8.5 CN8.6 CN8.7 CN8.8 D21.2(A) IC8.3(GND) IC8.5(GND) IC8.21(AGND) IC9.2(P:GND) IC9.3(A:+IN) Q31.E QG1.2(GND) ; also sheet 1,2,3,4,5,7,8,9,10,11,12,13
IR-LED: IC8.1(PD3(INT1/OC2B/PCINT19)) R51.1
M1-ADC: RN13.4 ; also sheet 1
M1-AOUT: CN8.4 IC8.24(PC1(ADC1/PCINT9)) RN13.5
M1-FLT: IC8.13(PB1(OC1A/PCINT1)) ; also sheet 1
M2-ADC: RN12.3 ; also sheet 2
M2-AOUT: CN7.3 IC8.26(PC3(ADC3/PCINT11)) RN12.6
M2-FLT: IC8.31(PD1(TXD/PCINT17)) ; also sheet 2
M3-ADC: RN12.4 ; also sheet 3
M3-AOUT: CN7.4 IC8.27(PC4(ADC4/SDA/PCINT12)) RN12.5
M3-FLT: IC8.32(PD2(INT0/PCINT18)) ; also sheet 3
M4-ADC: RN13.1 ; also sheet 4
M4-AOUT: CN8.1 IC8.23(PC0(ADC0/PCINT8)) RN13.8
M4-FLT: IC8.12(PB0(ICP1/CLKO/PCINT0)) ; also sheet 4
M5-ADC: RN12.1 ; also sheet 5
M5-AOUT: CN7.1 IC8.25(PC2(ADC2/PCINT10)) RN12.8
M5-FLT: IC8.30(PD0(RXD/PCINT16)) ; also sheet 5
M-AREF: C45.+ C46.1 D21.1(C) IC8.20(AREF) R46.1
M-AVCC: C44.1 IC8.18(AVCC) L1.2 R46.2
M-CS: IC8.14(PB2(SS/OC1B/PCINT2)) ; also sheet 9
M-LED1: IC8.9(PD5(T1/OC0B/PCINT21)) R44.1
M-LED2: IC8.10(PD6(AIN0/OC0A/PCINT22)) R45.1
M-RST: C42.1 IC8.29(PC6(/RESET/PCINT14)) R43.1 ; also sheet 9
M-XTAL: IC8.7(PB6(XTAL1/TOSC1/PCINT6)) QG1.3(OUT)
N$14: LED1.C R44.2
N$21: LED2.C R45.2
N$114: BD.2 C49.1 IC9.4(A:-IN) R49.1
N$181: Q31.B R51.2
N$182: BD.4 R50.2
N$184: Q31.C R50.1
N$185: C49.2 IC9.1(A:OUT) R48.1 R49.2
SPI3-MISO: IC8.16(PB4(MISO/PCINT4)) ; also sheet 7,9,13
SPI3-MOSI: IC8.15(PB3(MOSI/OC2A/PCINT3)) ; also sheet 7,9,13
SPI3-SCK: IC8.17(PB5(SCK/PCINT5)) ; also sheet 7,9,13
VOP1: C47.1 IC9.5(P:VCC) R47.2
Unconnected: CN7.2 CN8.2 CN8.3 IC8.8(PB7(XTAL2/TOSC2/PCINT7)) IC8.11(PD7(AIN1/PCINT23)) IC8.19(ADC6) IC8.22(ADC7) QG1.1(E/D) RN12.2 RN12.7 RN13.2 RN13.3 RN13.6 RN13.7

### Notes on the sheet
- Motor ATmega
- Optional Input Filter
- Ball Detection

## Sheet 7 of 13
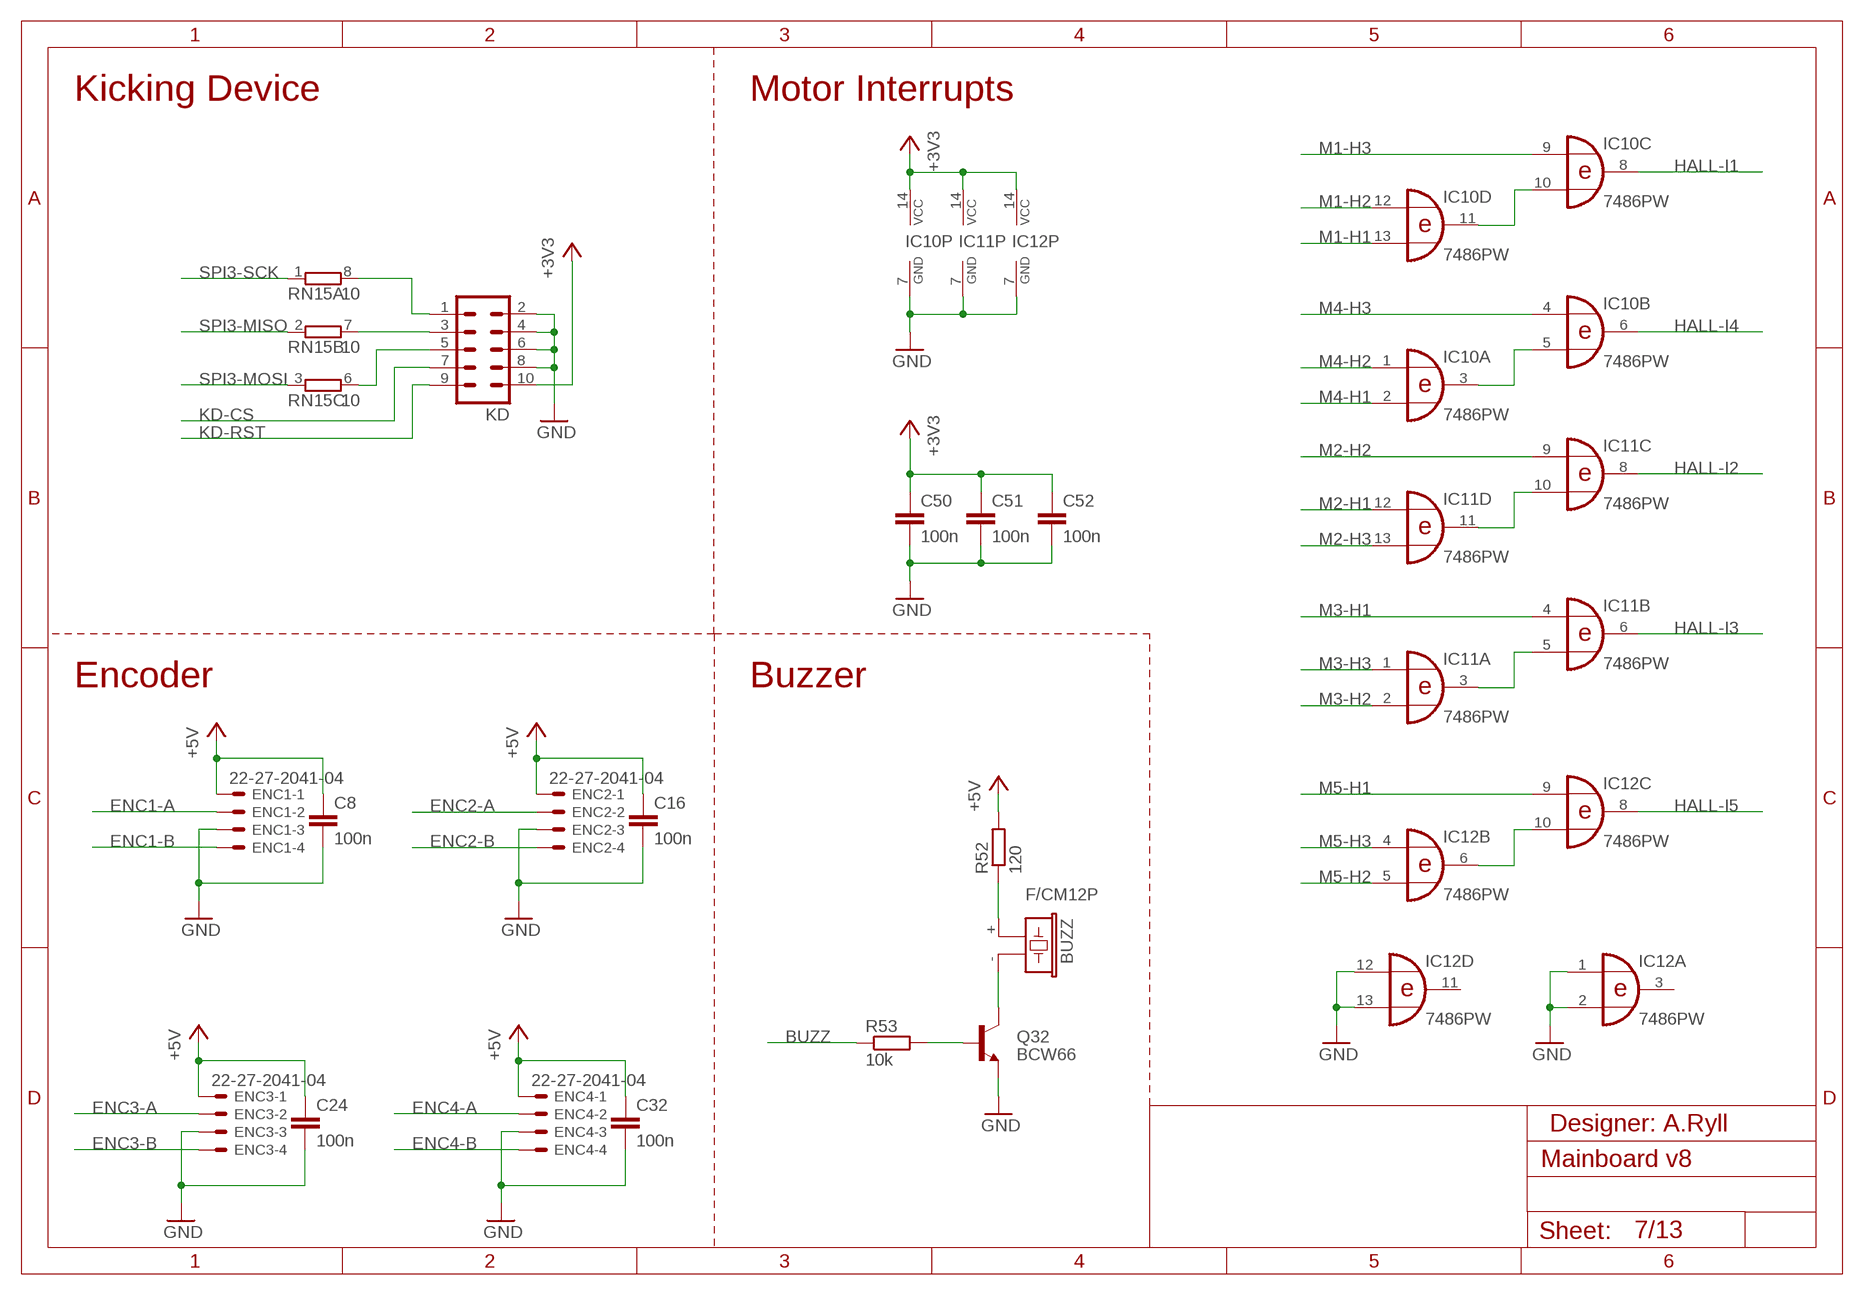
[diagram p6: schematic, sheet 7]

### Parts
BUZZ  F/CM12P  [F/CM12P]
C8  100n  C-EUC0805  [C0805]
C16  100n  C-EUC0805  [C0805]
C24  100n  C-EUC0805  [C0805]
C32  100n  C-EUC0805  [C0805]
C50  100n  C-EUC0805  [C0805]
C51  100n  C-EUC0805  [C0805]
C52  100n  C-EUC0805  [C0805]
ENC1  22-27-2041-04  [6410-04]
ENC2  22-27-2041-04  [6410-04]
ENC3  22-27-2041-04  [6410-04]
ENC4  22-27-2041-04  [6410-04]
IC10  7486PW  [TSSOP14]
IC11  7486PW  [TSSOP14]
IC12  7486PW  [TSSOP14]
KD  ML10  [ML10]
Q32  BCW66  BCW60SMD  [SOT23-BEC]
R52  120  R-EU_R0805  [R0805]
R53  10k  R-EU_R0805  [R0805]
RN15  10  4R-NCAY16  [CAY16]

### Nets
+3V3: C50.1 C51.1 C52.1 IC10.14(P:VCC) IC11.14(P:VCC) IC12.14(P:VCC) KD.10 ; also sheet 1,2,3,4,5,6,8,9,11,12,13
+5V: C8.1 C16.1 C24.1 C32.1 ENC1.1 ENC2.1 ENC3.1 ENC4.1 R52.2 ; also sheet 1,2,3,4,5,8,10,11
BUZZ: R53.1 ; also sheet 9
ENC1-A: ENC1.2 ; also sheet 9
ENC1-B: ENC1.4 ; also sheet 9
ENC2-A: ENC2.2 ; also sheet 9
ENC2-B: ENC2.4 ; also sheet 9
ENC3-A: ENC3.2 ; also sheet 9
ENC3-B: ENC3.4 ; also sheet 9
ENC4-A: ENC4.2 ; also sheet 9
ENC4-B: ENC4.4 ; also sheet 9
GND: C8.2 C16.2 C24.2 C32.2 C50.2 C51.2 C52.2 ENC1.3 ENC2.3 ENC3.3 ENC4.3 IC10.7(P:GND) IC11.7(P:GND) IC12.1(A:I0) IC12.2(A:I1) IC12.7(P:GND) IC12.12(D:I0) IC12.13(D:I1) KD.2 KD.4 KD.6 KD.8 Q32.E ; also sheet 1,2,3,4,5,6,8,9,10,11,12,13
HALL-I1: IC10.8(C:O) ; also sheet 9
HALL-I2: IC11.8(C:O) ; also sheet 9
HALL-I3: IC11.6(B:O) ; also sheet 9
HALL-I4: IC10.6(B:O) ; also sheet 9
HALL-I5: IC12.8(C:O) ; also sheet 9
KD-CS: KD.7 ; also sheet 9
KD-RST: KD.9 ; also sheet 9
M1-H1: IC10.13(D:I1) ; also sheet 1,9
M1-H2: IC10.12(D:I0) ; also sheet 1,9
M1-H3: IC10.9(C:I0) ; also sheet 1,9
M2-H1: IC11.12(D:I0) ; also sheet 2,9
M2-H2: IC11.9(C:I0) ; also sheet 2,9
M2-H3: IC11.13(D:I1) ; also sheet 2,9
M3-H1: IC11.4(B:I0) ; also sheet 3,9
M3-H2: IC11.2(A:I1) ; also sheet 3,9
M3-H3: IC11.1(A:I0) ; also sheet 3,9
M4-H1: IC10.2(A:I1) ; also sheet 4,9
M4-H2: IC10.1(A:I0) ; also sheet 4,9
M4-H3: IC10.4(B:I0) ; also sheet 4,9
M5-H1: IC12.9(C:I0) ; also sheet 5,9
M5-H2: IC12.5(B:I1) ; also sheet 5,9
M5-H3: IC12.4(B:I0) ; also sheet 5,9
N$22: KD.1 RN15.8
N$23: KD.3 RN15.7
N$24: KD.5 RN15.6
N$27: BUZZ.+ R52.1
N$28: BUZZ.- Q32.C
N$29: Q32.B R53.2
N$105: IC10.10(C:I1) IC10.11(D:O)
N$106: IC11.10(C:I1) IC11.11(D:O)
N$107: IC11.3(A:O) IC11.5(B:I1)
N$108: IC10.3(A:O) IC10.5(B:I1)
N$109: IC12.6(B:O) IC12.10(C:I1)
SPI3-MISO: RN15.2 ; also sheet 6,9,13
SPI3-MOSI: RN15.3 ; also sheet 6,9,13
SPI3-SCK: RN15.1 ; also sheet 6,9,13
Unconnected: IC12.3(A:O) IC12.11(D:O) RN15.4 RN15.5

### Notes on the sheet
- Kicking Device | Motor Interrupts
- Encoder | Buzzer
- Designer: A.Ryll

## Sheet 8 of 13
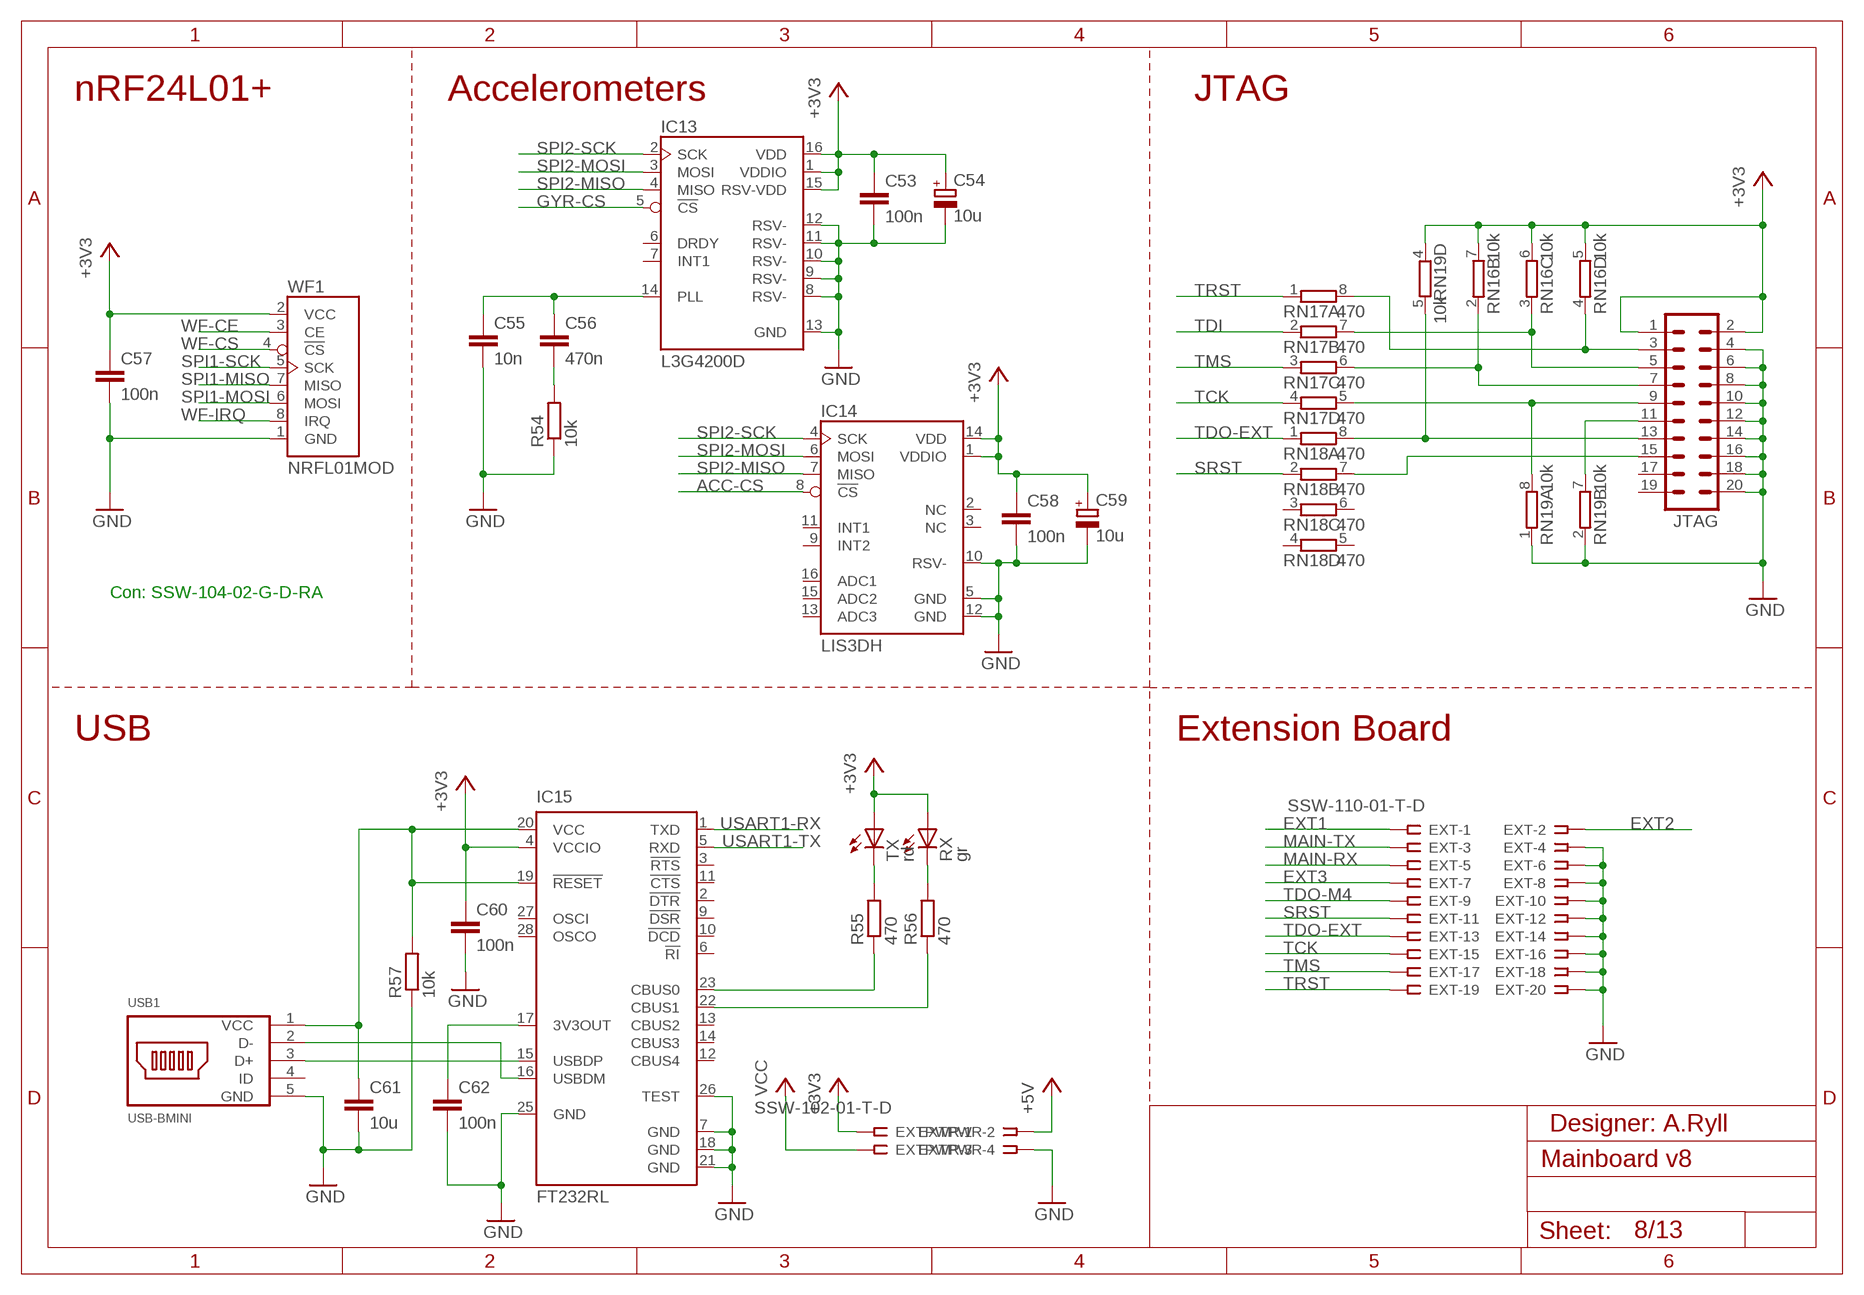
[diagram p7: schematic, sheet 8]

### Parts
C53  100n  C-EUC0805  [C0805]
C54  10u  CPOL-EUC  [PANASONIC_C]
C55  10n  C-EUC0805  [C0805]
C56  470n  C-EUC0805  [C0805]
C57  100n  C-EUC0805  [C0805]
C58  100n  C-EUC0805  [C0805]
C59  10u  CPOL-EUC  [PANASONIC_C]
C60  100n  C-EUC0805  [C0805]
C61  10u  C-EUC0805  [C0805]
C62  100n  C-EUC0805  [C0805]
EXT  SSW-110-01-T-D  SSW-110-02-S-D  [SSW-110-02-S-D]
EXTPWR  SSW-102-01-T-D  SSW-102-02-S-D  [SSW-102-02-S-D]
IC13  L3G4200D  [LGA16L]
IC14  LIS3DH  [LGA16]
IC15  FT232RL  [SSOP28]
JTAG  ML20  [ML20]
R54  10k  R-EU_R0805  [R0805]
R55  470  R-EU_R0805  [R0805]
R56  470  R-EU_R0805  [R0805]
R57  10k  R-EU_R0805  [R0805]
RN16  10k  4R-NCAY16  [CAY16]
RN17  470  4R-NCAY16  [CAY16]
RN18  470  4R-NCAY16  [CAY16]
RN19  10k  4R-NCAY16  [CAY16]
RX  gr  LEDCHIP-LED0805  [CHIP-LED0805]
TX  rd  LEDCHIP-LED0805  [CHIP-LED0805]
USB1  USB-BMINI  [USB-BMINI]
WF1  NRFL01MOD  [NRF24L01MOD]

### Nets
3V3OUT: C62.1 IC15.17(3V3OUT)
+3V3: C53.1 C54.+ C57.1 C58.1 C59.+ C60.1 EXTPWR.1 IC13.1(VDDIO) IC13.15(RSV-VDD) IC13.16(VDD) IC14.1(VDDIO) IC14.14(VDD) IC15.4(VCCIO) JTAG.1 JTAG.2 RN16.5 RN16.6 RN16.7 RN19.4 RX.A TX.A WF1.2(VCC) ; also sheet 1,2,3,4,5,6,7,9,11,12,13
+5V: EXTPWR.2 ; also sheet 1,2,3,4,5,7,10,11
ACC-CS: IC14.8(!CS) ; also sheet 9
EXT1: EXT.1 ; also sheet 9
EXT2: EXT.2 ; also sheet 9
EXT3: EXT.7 ; also sheet 9
GND: C53.2 C54.- C55.2 C57.2 C58.2 C59.- C60.2 C61.2 C62.2 EXT.4 EXT.6 EXT.8 EXT.10 EXT.12 EXT.14 EXT.16 EXT.18 EXT.20 EXTPWR.4 IC13.8(RSV-) IC13.9(RSV-) IC13.10(RSV-) IC13.11(RSV-) IC13.12(RSV-) IC13.13(GND) IC14.5(GND) IC14.10(RSV-) IC14.12(GND) IC15.7(GND) IC15.18(GND) IC15.21(GND) IC15.25(GND) IC15.26(TEST) JTAG.4 JTAG.6 JTAG.8 JTAG.10 JTAG.12 JTAG.14 JTAG.16 JTAG.18 JTAG.20 R54.1 R57.1 RN19.1 RN19.2 USB1.5(GND) WF1.1(GND) ; also sheet 1,2,3,4,5,6,7,9,10,11,12,13
GYR-CS: IC13.5(!CS) ; also sheet 9
JTAG-SRST: JTAG.15 RN18.7
JTAG-TCK: JTAG.9 RN17.5 RN19.8
JTAG-TDI: JTAG.5 RN16.3 RN17.7
JTAG-TDO: JTAG.13 RN18.8 RN19.5
JTAG-TMS: JTAG.7 RN16.2 RN17.6
JTAG-TRST: JTAG.3 RN16.4 RN17.8
MAIN-RX: EXT.5 ; also sheet 9
MAIN-TX: EXT.3 ; also sheet 9
N$26: R55.2 TX.C
N$30: R56.2 RX.C
N$75: IC15.15(USBDP) USB1.3(D+)
N$81: IC15.23(CBUS0) R55.1
N$101: IC15.22(CBUS1) R56.1
N$155: C56.2 R54.2
N$173: JTAG.11 RN19.7
N$176: C55.1 C56.1 IC13.14(PLL)
N$179: IC15.16(USBDM) USB1.2(D-)
SPI1-MISO: WF1.7(MISO) ; also sheet 9
SPI1-MOSI: WF1.6(MOSI) ; also sheet 9
SPI1-SCK: WF1.5(SCK) ; also sheet 9
SPI2-MISO: IC13.4(MISO) IC14.7(MISO) ; also sheet 9
SPI2-MOSI: IC13.3(MOSI) IC14.6(MOSI) ; also sheet 9
SPI2-SCK: IC13.2(SCK) IC14.4(SCK) ; also sheet 9
SRST: EXT.11 RN18.2 ; also sheet 9
TCK: EXT.15 RN17.4 ; also sheet 9
TDI: RN17.2 ; also sheet 9
TDO-EXT: EXT.13 RN18.1
TDO-M4: EXT.9 ; also sheet 9
TMS: EXT.17 RN17.3 ; also sheet 9
TRST: EXT.19 RN17.1 ; also sheet 9
USART1-RX: IC15.1(TXD) ; also sheet 9
USART1-TX: IC15.5(RXD) ; also sheet 9
VCC: EXTPWR.3 ; also sheet 1,2,3,4,5,10
VCCUSB: C61.1 IC15.19(!RESET) IC15.20(VCC) R57.2 USB1.1(VCC)
WF-CE: WF1.3(CE) ; also sheet 9
WF-CS: WF1.4(!CS) ; also sheet 9
WF-IRQ: WF1.8(IRQ) ; also sheet 9
Unconnected: IC13.6(DRDY) IC13.7(INT1) IC14.2(NC) IC14.3(NC) IC14.9(INT2) IC14.11(INT1) IC14.13(ADC3) IC14.15(ADC2) IC14.16(ADC1) IC15.2(!DTR) IC15.3(!RTS) IC15.6(!RI) IC15.9(!DSR) IC15.10(!DCD) IC15.11(!CTS) IC15.12(CBUS4) IC15.13(CBUS2) IC15.14(CBUS3) IC15.27(OSCI) IC15.28(OSCO) JTAG.17 JTAG.19 RN16.1 RN16.8 RN18.3 RN18.4 RN18.5 RN18.6 USB1.4(ID)

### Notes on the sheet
- nRF24L01+ | Accelerometers | JTAG
- Con: SSW-104-02-G-D-RA
- USB | Extension Board
- Designer: A.Ryll

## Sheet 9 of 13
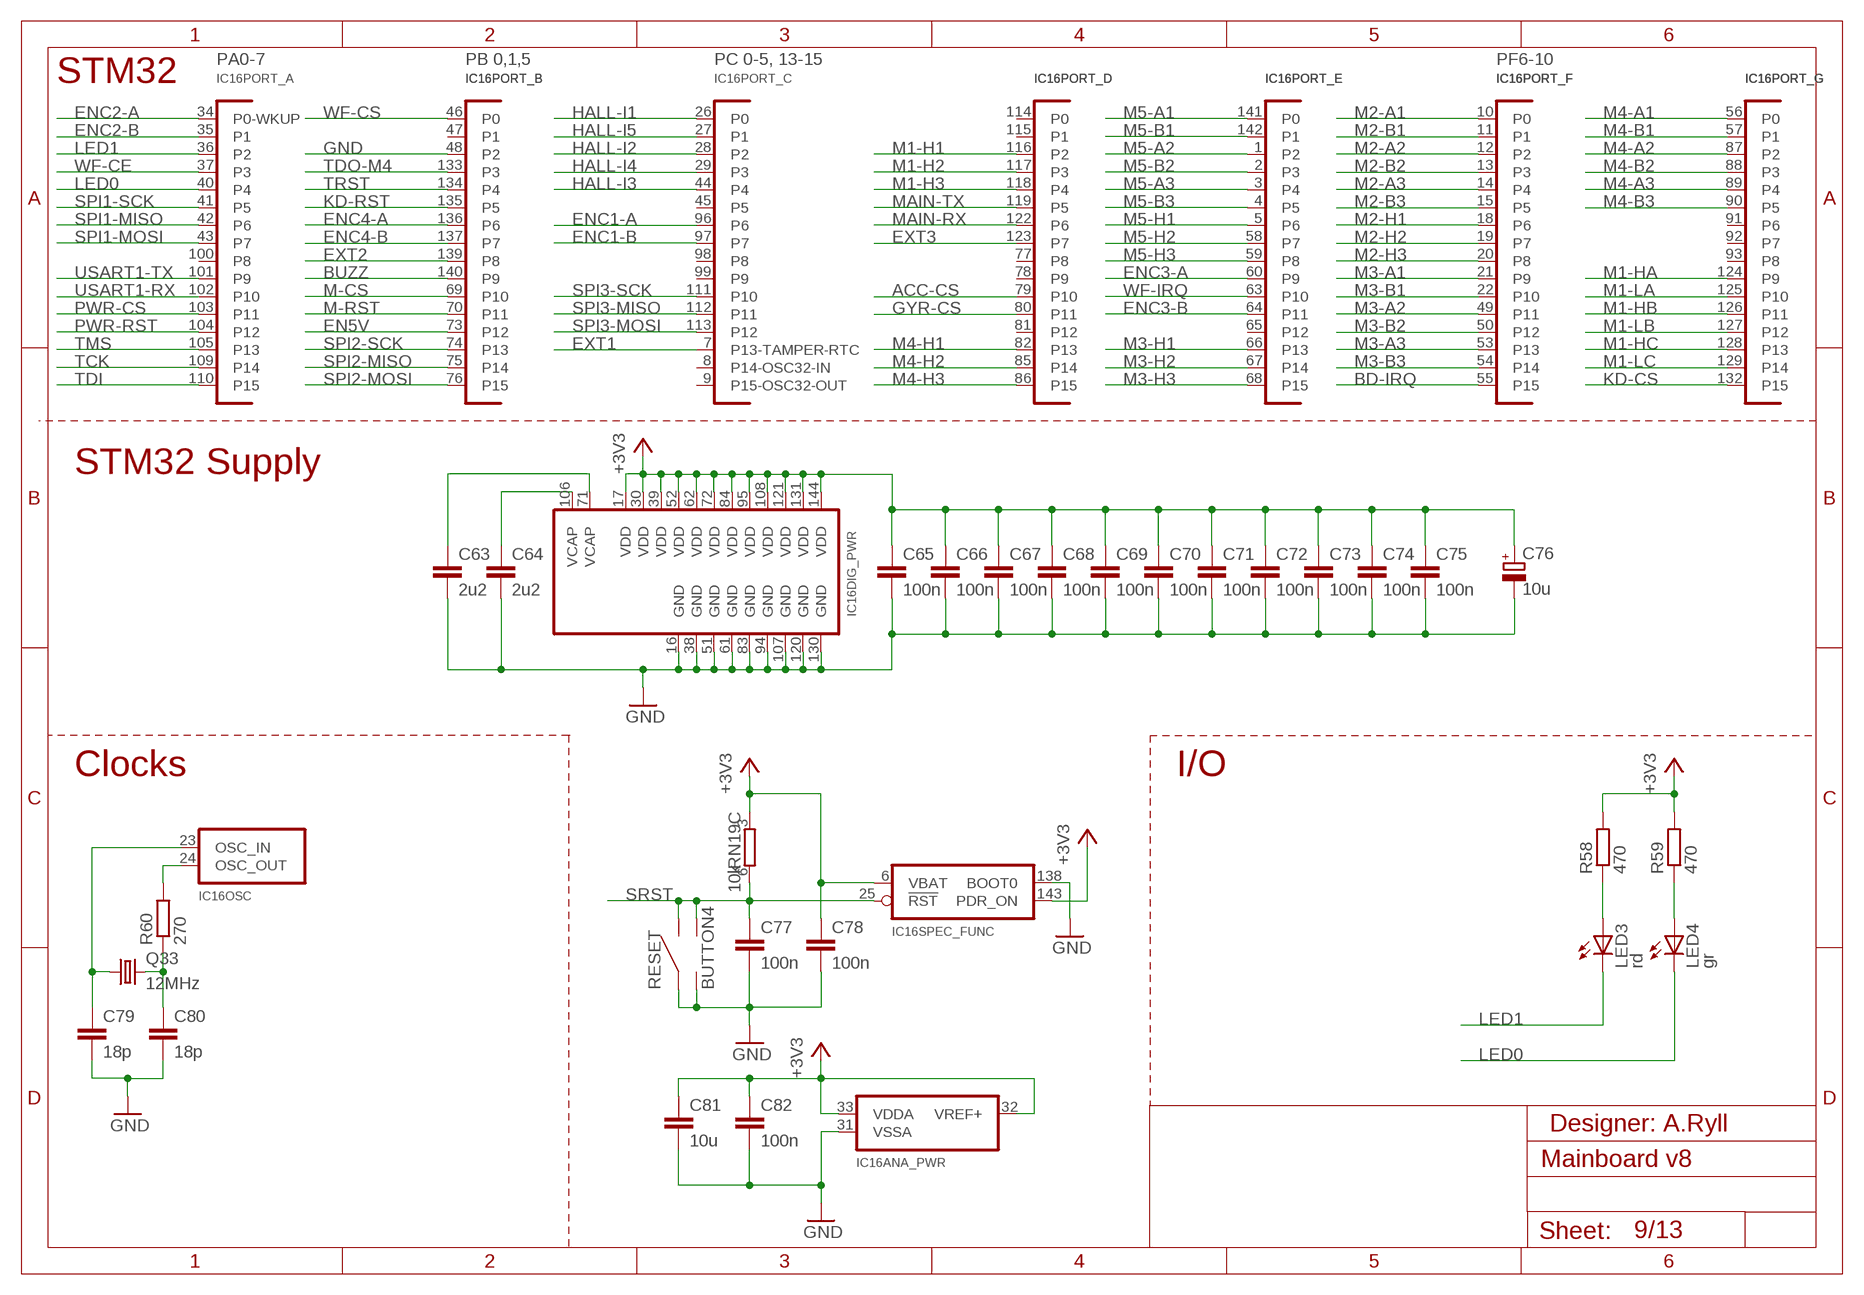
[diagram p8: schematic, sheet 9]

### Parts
C63  2u2  C-EUC0805  [C0805]
C64  2u2  C-EUC0805  [C0805]
C65  100n  C-EUC0805  [C0805]
C66  100n  C-EUC0805  [C0805]
C67  100n  C-EUC0805  [C0805]
C68  100n  C-EUC0805  [C0805]
C69  100n  C-EUC0805  [C0805]
C70  100n  C-EUC0805  [C0805]
C71  100n  C-EUC0805  [C0805]
C72  100n  C-EUC0805  [C0805]
C73  100n  C-EUC0805  [C0805]
C74  100n  C-EUC0805  [C0805]
C75  100n  C-EUC0805  [C0805]
C76  10u  CPOL-EUC  [PANASONIC_C]
C77  100n  C-EUC0805  [C0805]
C78  100n  C-EUC0805  [C0805]
C79  18p  C-EUC0805  [C0805]
C80  18p  C-EUC0805  [C0805]
C81  10u  C-EUC0805  [C0805]
C82  100n  C-EUC0805  [C0805]
IC16  STM32F40_Z  [SQFP-S-20X20-144]
LED3  rd  LEDCHIP-LED0805  [CHIP-LED0805]
LED4  gr  LEDCHIP-LED0805  [CHIP-LED0805]
Q33  12MHz  CRYSTAL7A  [CRYSTAL-7A]
R58  470  R-EU_R0805  [R0805]
R59  470  R-EU_R0805  [R0805]
R60  270  R-EU_R0805  [R0805]
RESET  BUTTON4  [BUTTON4]

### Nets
+3V3: C65.1 C66.1 C67.1 C68.1 C69.1 C70.1 C71.1 C72.1 C73.1 C74.1 C75.1 C76.+ C78.1 C81.1 C82.1 IC16.6(SPEC_FUNC:VBAT) IC16.17(DIG_PWR:VDD) IC16.30(DIG_PWR:VDD) IC16.32(ANA_PWR:VREF+) IC16.33(ANA_PWR:VDDA) IC16.39(DIG_PWR:VDD) IC16.52(DIG_PWR:VDD) IC16.62(DIG_PWR:VDD) IC16.72(DIG_PWR:VDD) IC16.84(DIG_PWR:VDD) IC16.95(DIG_PWR:VDD) IC16.108(DIG_PWR:VDD) IC16.121(DIG_PWR:VDD) IC16.131(DIG_PWR:VDD) IC16.143(SPEC_FUNC:PDR_ON) IC16.144(DIG_PWR:VDD) R58.2 R59.2 RN19.3 ; also sheet 1,2,3,4,5,6,7,8,11,12,13
ACC-CS: IC16.79(PORT_D:P10) ; also sheet 8
BD-IRQ: IC16.55(PORT_F:P15) ; also sheet 6
BUZZ: IC16.140(PORT_B:P9) ; also sheet 7
EN5V: IC16.73(PORT_B:P12) ; also sheet 11
ENC1-A: IC16.96(PORT_C:P6) ; also sheet 7
ENC1-B: IC16.97(PORT_C:P7) ; also sheet 7
ENC2-A: IC16.34(PORT_A:P0-WKUP) ; also sheet 7
ENC2-B: IC16.35(PORT_A:P1) ; also sheet 7
ENC3-A: IC16.60(PORT_E:P9) ; also sheet 7
ENC3-B: IC16.64(PORT_E:P11) ; also sheet 7
ENC4-A: IC16.136(PORT_B:P6) ; also sheet 7
ENC4-B: IC16.137(PORT_B:P7) ; also sheet 7
EXT1: IC16.7(PORT_C:P13-TAMPER-RTC) ; also sheet 8
EXT2: IC16.139(PORT_B:P8) ; also sheet 8
EXT3: IC16.123(PORT_D:P7) ; also sheet 8
GND: C63.2 C64.2 C65.2 C66.2 C67.2 C68.2 C69.2 C70.2 C71.2 C72.2 C73.2 C74.2 C75.2 C76.- C77.2 C78.2 C79.2 C80.2 C81.2 C82.2 IC16.16(DIG_PWR:GND) IC16.31(ANA_PWR:VSSA) IC16.38(DIG_PWR:GND) IC16.48(PORT_B:P2) IC16.51(DIG_PWR:GND) IC16.61(DIG_PWR:GND) IC16.83(DIG_PWR:GND) IC16.94(DIG_PWR:GND) IC16.107(DIG_PWR:GND) IC16.120(DIG_PWR:GND) IC16.130(DIG_PWR:GND) IC16.138(SPEC_FUNC:BOOT0) RESET.1 RESET.2 ; also sheet 1,2,3,4,5,6,7,8,10,11,12,13
GYR-CS: IC16.80(PORT_D:P11) ; also sheet 8
HALL-I1: IC16.26(PORT_C:P0) ; also sheet 7
HALL-I2: IC16.28(PORT_C:P2) ; also sheet 7
HALL-I3: IC16.44(PORT_C:P4) ; also sheet 7
HALL-I4: IC16.29(PORT_C:P3) ; also sheet 7
HALL-I5: IC16.27(PORT_C:P1) ; also sheet 7
KD-CS: IC16.132(PORT_G:P15) ; also sheet 7
KD-RST: IC16.135(PORT_B:P5) ; also sheet 7
LED0: IC16.40(PORT_A:P4) LED4.C
LED1: IC16.36(PORT_A:P2) LED3.C
M1-H1: IC16.116(PORT_D:P2) ; also sheet 1,7
M1-H2: IC16.117(PORT_D:P3) ; also sheet 1,7
M1-H3: IC16.118(PORT_D:P4) ; also sheet 1,7
M1-HA: IC16.124(PORT_G:P9) ; also sheet 1
M1-HB: IC16.126(PORT_G:P11) ; also sheet 1
M1-HC: IC16.128(PORT_G:P13) ; also sheet 1
M1-LA: IC16.125(PORT_G:P10) ; also sheet 1
M1-LB: IC16.127(PORT_G:P12) ; also sheet 1
M1-LC: IC16.129(PORT_G:P14) ; also sheet 1
M2-A1: IC16.10(PORT_F:P0) ; also sheet 2
M2-A2: IC16.12(PORT_F:P2) ; also sheet 2
M2-A3: IC16.14(PORT_F:P4) ; also sheet 2
M2-B1: IC16.11(PORT_F:P1) ; also sheet 2
M2-B2: IC16.13(PORT_F:P3) ; also sheet 2
M2-B3: IC16.15(PORT_F:P5) ; also sheet 2
M2-H1: IC16.18(PORT_F:P6) ; also sheet 2,7
M2-H2: IC16.19(PORT_F:P7) ; also sheet 2,7
M2-H3: IC16.20(PORT_F:P8) ; also sheet 2,7
M3-A1: IC16.21(PORT_F:P9) ; also sheet 3
M3-A2: IC16.49(PORT_F:P11) ; also sheet 3
M3-A3: IC16.53(PORT_F:P13) ; also sheet 3
M3-B1: IC16.22(PORT_F:P10) ; also sheet 3
M3-B2: IC16.50(PORT_F:P12) ; also sheet 3
M3-B3: IC16.54(PORT_F:P14) ; also sheet 3
M3-H1: IC16.66(PORT_E:P13) ; also sheet 3,7
M3-H2: IC16.67(PORT_E:P14) ; also sheet 3,7
M3-H3: IC16.68(PORT_E:P15) ; also sheet 3,7
M4-A1: IC16.56(PORT_G:P0) ; also sheet 4
M4-A2: IC16.87(PORT_G:P2) ; also sheet 4
M4-A3: IC16.89(PORT_G:P4) ; also sheet 4
M4-B1: IC16.57(PORT_G:P1) ; also sheet 4
M4-B2: IC16.88(PORT_G:P3) ; also sheet 4
M4-B3: IC16.90(PORT_G:P5) ; also sheet 4
M4-H1: IC16.82(PORT_D:P13) ; also sheet 4,7
M4-H2: IC16.85(PORT_D:P14) ; also sheet 4,7
M4-H3: IC16.86(PORT_D:P15) ; also sheet 4,7
M5-A1: IC16.141(PORT_E:P0) ; also sheet 5
M5-A2: IC16.1(PORT_E:P2) ; also sheet 5
M5-A3: IC16.3(PORT_E:P4) ; also sheet 5
M5-B1: IC16.142(PORT_E:P1) ; also sheet 5
M5-B2: IC16.2(PORT_E:P3) ; also sheet 5
M5-B3: IC16.4(PORT_E:P5) ; also sheet 5
M5-H1: IC16.5(PORT_E:P6) ; also sheet 5,7
M5-H2: IC16.58(PORT_E:P7) ; also sheet 5,7
M5-H3: IC16.59(PORT_E:P8) ; also sheet 5,7
M-CS: IC16.69(PORT_B:P10) ; also sheet 6
M-RST: IC16.70(PORT_B:P11) ; also sheet 6
MAIN-RX: IC16.122(PORT_D:P6) ; also sheet 8
MAIN-TX: IC16.119(PORT_D:P5) ; also sheet 8
N$20: C64.1 IC16.106(DIG_PWR:VCAP)
N$25: LED3.A R58.1
N$120: LED4.A R59.1
N$165: IC16.24(OSC:OSC_OUT) R60.2
N$168: C79.1 IC16.23(OSC:OSC_IN) Q33.1
N$169: C80.1 Q33.2 R60.1
N$180: C63.1 IC16.71(DIG_PWR:VCAP)
PWR-CS: IC16.103(PORT_A:P11) ; also sheet 13
PWR-RST: IC16.104(PORT_A:P12) ; also sheet 13
SPI1-MISO: IC16.42(PORT_A:P6) ; also sheet 8
SPI1-MOSI: IC16.43(PORT_A:P7) ; also sheet 8
SPI1-SCK: IC16.41(PORT_A:P5) ; also sheet 8
SPI2-MISO: IC16.75(PORT_B:P14) ; also sheet 8
SPI2-MOSI: IC16.76(PORT_B:P15) ; also sheet 8
SPI2-SCK: IC16.74(PORT_B:P13) ; also sheet 8
SPI3-MISO: IC16.112(PORT_C:P11) ; also sheet 6,7,13
SPI3-MOSI: IC16.113(PORT_C:P12) ; also sheet 6,7,13
SPI3-SCK: IC16.111(PORT_C:P10) ; also sheet 6,7,13
SRST: C77.1 IC16.25(SPEC_FUNC:!RST) RESET.3 RESET.4 RN19.6 ; also sheet 8
TCK: IC16.109(PORT_A:P14) ; also sheet 8
TDI: IC16.110(PORT_A:P15) ; also sheet 8
TDO-M4: IC16.133(PORT_B:P3) ; also sheet 8
TMS: IC16.105(PORT_A:P13) ; also sheet 8
TRST: IC16.134(PORT_B:P4) ; also sheet 8
USART1-RX: IC16.102(PORT_A:P10) ; also sheet 8
USART1-TX: IC16.101(PORT_A:P9) ; also sheet 8
WF-CE: IC16.37(PORT_A:P3) ; also sheet 8
WF-CS: IC16.46(PORT_B:P0) ; also sheet 8
WF-IRQ: IC16.63(PORT_E:P10) ; also sheet 8
Unconnected: IC16.8(PORT_C:P14-OSC32-IN) IC16.9(PORT_C:P15-OSC32-OUT) IC16.45(PORT_C:P5) IC16.47(PORT_B:P1) IC16.65(PORT_E:P12) IC16.77(PORT_D:P8) IC16.78(PORT_D:P9) IC16.81(PORT_D:P12) IC16.91(PORT_G:P6) IC16.92(PORT_G:P7) IC16.93(PORT_G:P8) IC16.98(PORT_C:P8) IC16.99(PORT_C:P9) IC16.100(PORT_A:P8) IC16.114(PORT_D:P0) IC16.115(PORT_D:P1)

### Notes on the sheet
- PA0-7 | PB 0,1,5 | PC 0-5, 13-15 | PF6-10
- STM32
- STM32 Supply
- Clocks | I/O
- Designer: A.Ryll

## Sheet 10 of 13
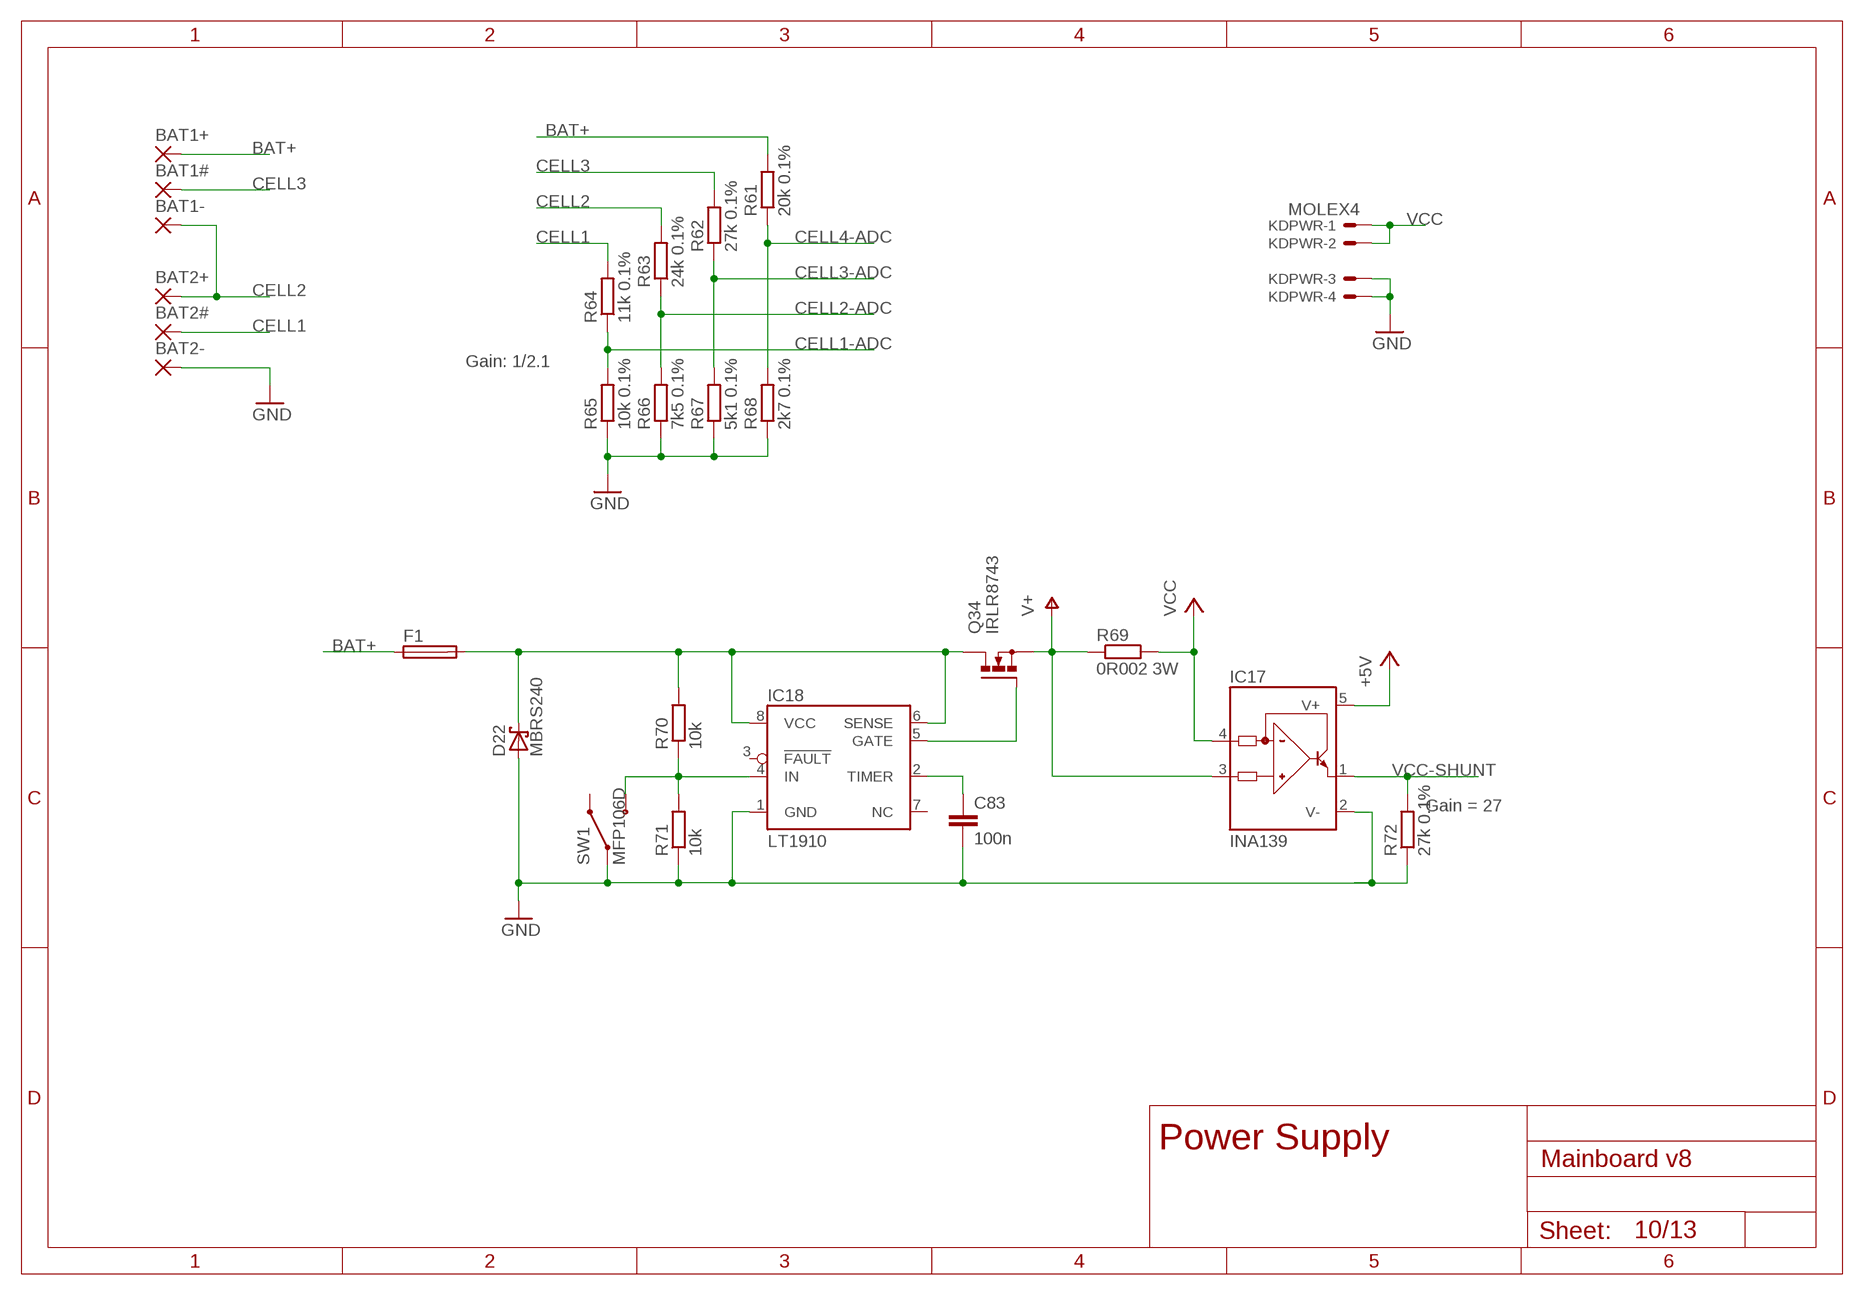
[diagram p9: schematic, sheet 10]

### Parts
BAT1#  WIREPAD2,54/1,0  [2,54/1,0]
BAT1+  WIREPAD2,54/1,5  [2,54/1,5]
BAT1-  WIREPAD2,54/1,5  [2,54/1,5]
BAT2#  WIREPAD2,54/1,0  [2,54/1,0]
BAT2+  WIREPAD2,54/1,5  [2,54/1,5]
BAT2-  WIREPAD2,54/1,5  [2,54/1,5]
C83  100n  C-EUC0805  [C0805]
D22  MBRS240  SCHOTTKY-DIODESMD  [SMB]
F1  FUSE5X202  [FUSE20X5-2]
IC17  INA139  INA138  [SOT23-5]
IC18  LT1910  [SOIC8]
KDPWR  MOLEX4  22-27-2041-04  [6410-04]
Q34  IRLR8743  NMOSD  [D-PAK_TO252AA]
R61  20k 0.1%  R-EU_R0805  [R0805]
R62  27k 0.1%  R-EU_R0805  [R0805]
R63  24k 0.1%  R-EU_R0805  [R0805]
R64  11k 0.1%  R-EU_R0805  [R0805]
R65  10k 0.1%  R-EU_R0805  [R0805]
R66  7k5 0.1%  R-EU_R0805  [R0805]
R67  5k1 0.1%  R-EU_R0805  [R0805]
R68  2k7 0.1%  R-EU_R0805  [R0805]
R69  0R002 3W  R-EU_R2512  [R2512]
R70  10k  R-EU_R0805  [R0805]
R71  10k  R-EU_R0805  [R0805]
R72  27k 0.1%  R-EU_R0805  [R0805]
SW1  MFP106D  SPDTKNIT  [SW-KNITTER]

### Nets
+5V: IC17.5(V+) ; also sheet 1,2,3,4,5,7,8,11
BAT+: BAT1+.P$1(P) F1.P$1 R61.2
BAT-FS: D22.C F1.P$2 IC18.6(SENSE) IC18.8(VCC) Q34.4(D) R70.2
CELL1: BAT2#.1(P) R64.2
CELL1-ADC: R64.1 R65.2 ; also sheet 12
CELL2: BAT1-.P$1(P) BAT2+.P$1(P) R63.2
CELL2-ADC: R63.1 R66.2 ; also sheet 12
CELL3: BAT1#.1(P) R62.2
CELL3-ADC: R62.1 R67.2 ; also sheet 12
CELL4-ADC: R61.1 R68.2 ; also sheet 12
GND: BAT2-.P$1(P) C83.2 D22.A IC17.2(V-) IC18.1(GND) KDPWR.3 KDPWR.4 R65.1 R66.1 R67.1 R68.1 R71.1 R72.1 SW1.2(E) ; also sheet 1,2,3,4,5,6,7,8,9,11,12,13
N$6: C83.1 IC18.2(TIMER)
N$15: IC18.4(IN) R70.1 R71.2 SW1.3(A2)
N$157: IC18.5(GATE) Q34.1(G)
V+: IC17.3(IN+) Q34.3(S) R69.1 ; also sheet 11
VCC: IC17.4(IN-) KDPWR.1 KDPWR.2 R69.2 ; also sheet 1,2,3,4,5,8
VCC-SHUNT: IC17.1(OUT) R72.2 ; also sheet 12
Unconnected: IC18.3(!FAULT) IC18.7(NC) SW1.1(A1)

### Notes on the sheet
- Gain: 1/2.1
- Gain = 27
- Power Supply

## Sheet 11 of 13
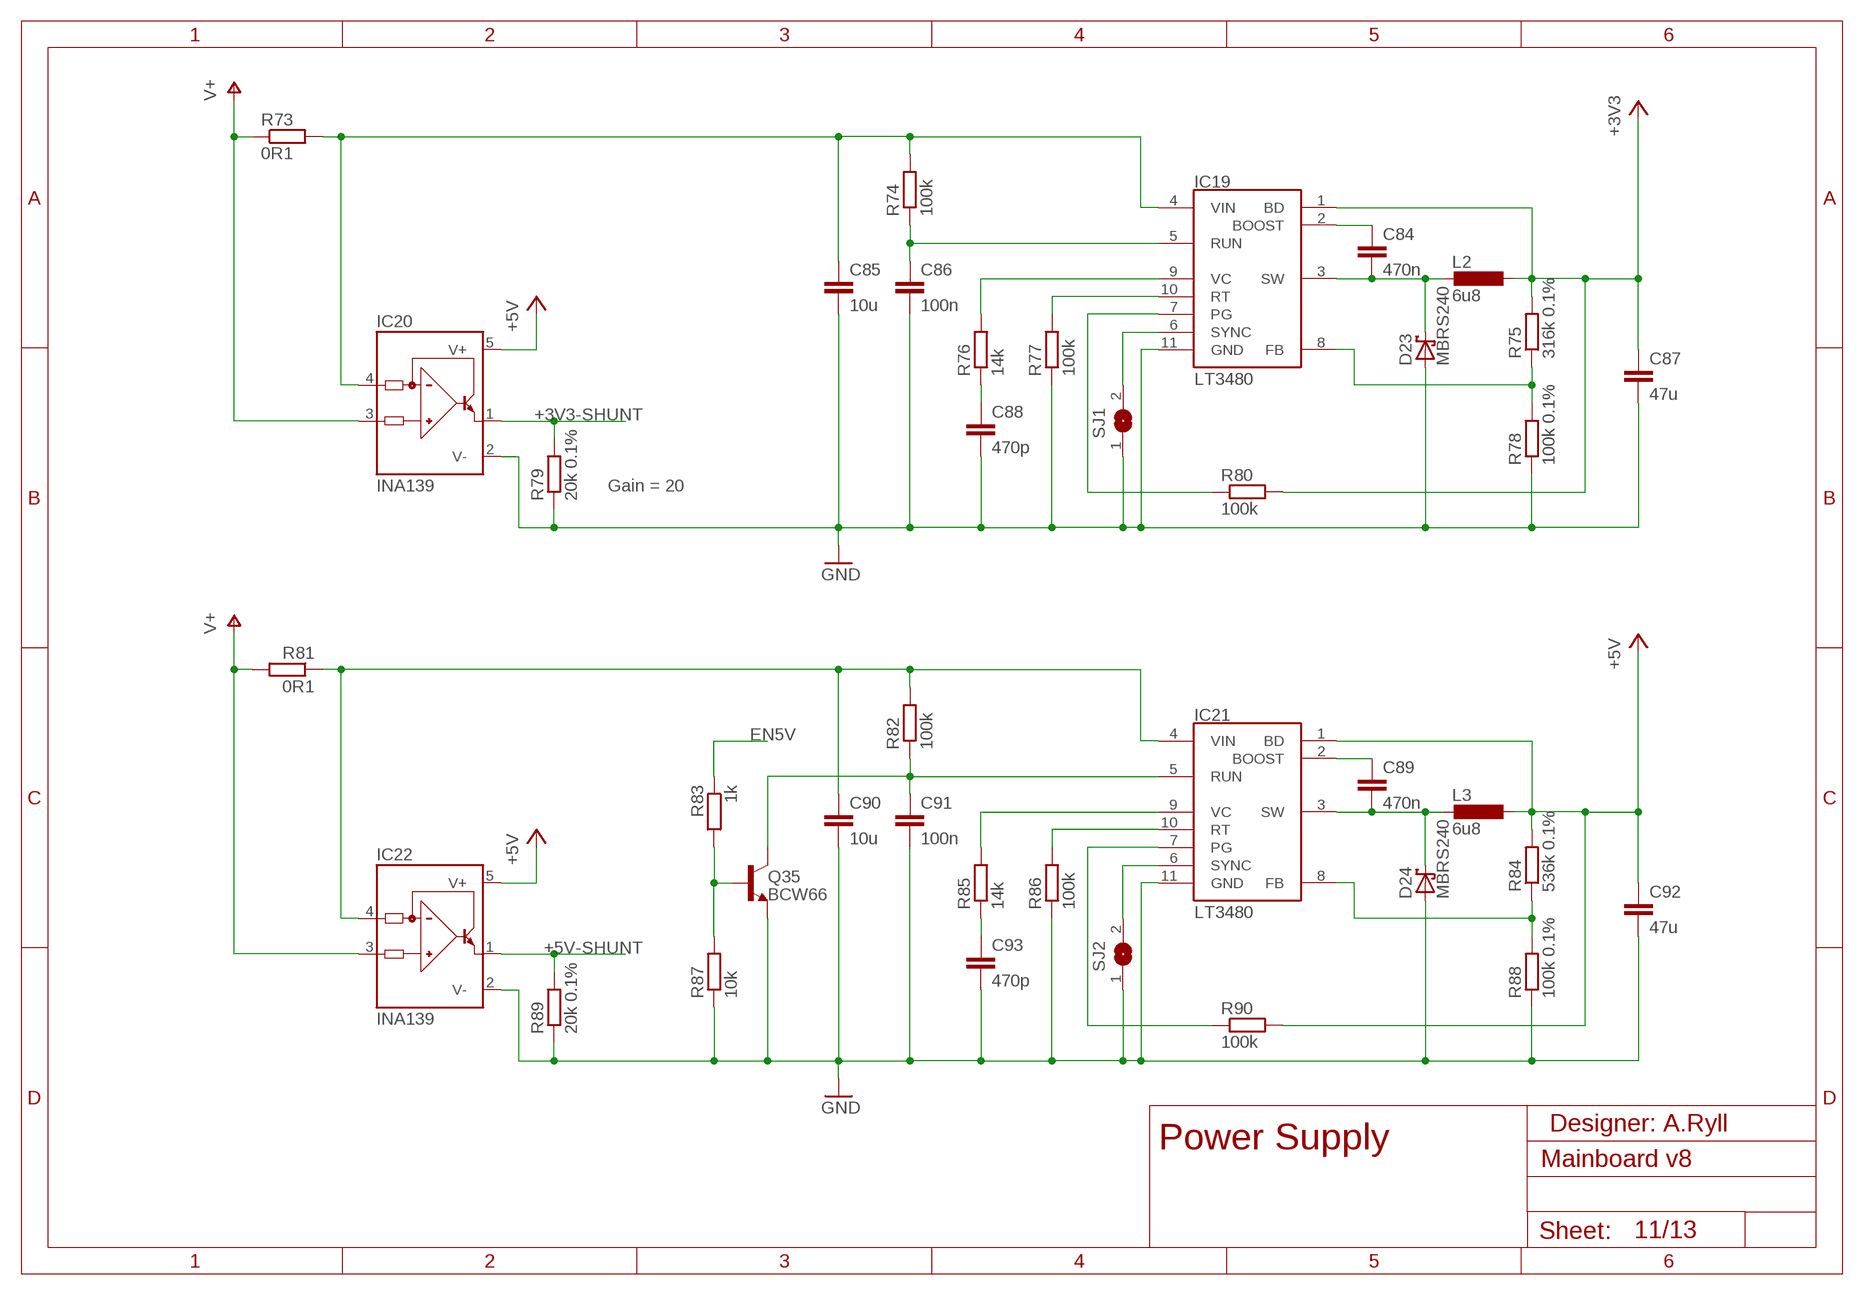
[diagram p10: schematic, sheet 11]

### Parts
C84  470n  C-EUC0805  [C0805]
C85  10u  C-EUC1210  [C1210]
C86  100n  C-EUC0805  [C0805]
C87  47u  C-EUC1210  [C1210]
C88  470p  C-EUC0805  [C0805]
C89  470n  C-EUC0805  [C0805]
C90  10u  C-EUC1210  [C1210]
C91  100n  C-EUC0805  [C0805]
C92  47u  C-EUC1210  [C1210]
C93  470p  C-EUC0805  [C0805]
D23  MBRS240  SCHOTTKY-DIODESMD  [SMB]
D24  MBRS240  SCHOTTKY-DIODESMD  [SMB]
IC19  LT3480  [MSOP10]
IC20  INA139  INA138  [SOT23-5]
IC21  LT3480  [MSOP10]
IC22  INA139  INA138  [SOT23-5]
L2  6u8  LP  [L-ELL6]
L3  6u8  LP  [L-ELL6]
Q35  BCW66  BCW60SMD  [SOT23-BEC]
R73  0R1  R-EU_R2512  [R2512]
R74  100k  R-EU_R0805  [R0805]
R75  316k 0.1%  R-EU_R0805  [R0805]
R76  14k  R-EU_R0805  [R0805]
R77  100k  R-EU_R0805  [R0805]
R78  100k 0.1%  R-EU_R0805  [R0805]
R79  20k 0.1%  R-EU_R0805  [R0805]
R80  100k  R-EU_R0805  [R0805]
R81  0R1  R-EU_R2512  [R2512]
R82  100k  R-EU_R0805  [R0805]
R83  1k  R-EU_R0805  [R0805]
R84  536k 0.1%  R-EU_R0805  [R0805]
R85  14k  R-EU_R0805  [R0805]
R86  100k  R-EU_R0805  [R0805]
R87  10k  R-EU_R0805  [R0805]
R88  100k 0.1%  R-EU_R0805  [R0805]
R89  20k 0.1%  R-EU_R0805  [R0805]
R90  100k  R-EU_R0805  [R0805]
SJ1  SJ  [SJ]
SJ2  SJ  [SJ]

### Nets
+3V3: C87.1 IC19.1(BD) L2.P$1 R75.2 R80.2 ; also sheet 1,2,3,4,5,6,7,8,9,12,13
+3V3-LOW: C85.1 IC19.4(VIN) IC20.4(IN-) R73.2 R74.2
+3V3-SHUNT: IC20.1(OUT) R79.2 ; also sheet 12
+5V: C92.1 IC20.5(V+) IC21.1(BD) IC22.5(V+) L3.P$1 R84.2 R90.2 ; also sheet 1,2,3,4,5,7,8,10
+5V-LOW: C90.1 IC21.4(VIN) IC22.4(IN-) R81.1 R82.2
+5V-SHUNT: IC22.1(OUT) R89.2 ; also sheet 12
EN: C91.1 IC21.5(RUN) Q35.C R82.1
EN5V: R83.1 ; also sheet 9
GND: C85.2 C86.2 C87.2 C88.2 C90.2 C91.2 C92.2 C93.2 D23.A D24.A IC19.11(GND) IC20.2(V-) IC21.11(GND) IC22.2(V-) Q35.E R77.1 R78.1 R79.1 R86.1 R87.1 R88.1 R89.1 SJ1.1 SJ2.1 ; also sheet 1,2,3,4,5,6,7,8,9,10,12,13
N$7: Q35.B R83.2 R87.2
N$79: IC19.6(SYNC) SJ1.2
N$115: IC21.6(SYNC) SJ2.2
N$150: C86.1 IC19.5(RUN) R74.1
N$151: IC19.9(VC) R76.2
N$174: IC19.10(RT) R77.2
N$175: C88.1 R76.1
N$187: IC19.7(PG) R80.1
N$197: C84.1 IC19.2(BOOST)
N$198: C84.2 D23.C IC19.3(SW) L2.P$2
N$200: IC19.8(FB) R75.1 R78.2
N$201: IC21.9(VC) R85.2
N$202: IC21.10(RT) R86.2
N$203: C93.1 R85.1
N$204: IC21.7(PG) R90.1
N$205: C89.1 IC21.2(BOOST)
N$206: C89.2 D24.C IC21.3(SW) L3.P$2
N$207: IC21.8(FB) R84.1 R88.2
V+: IC20.3(IN+) IC22.3(IN+) R73.1 R81.2 ; also sheet 10

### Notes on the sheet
- Gain = 20
- Designer: A.Ryll
- Power Supply

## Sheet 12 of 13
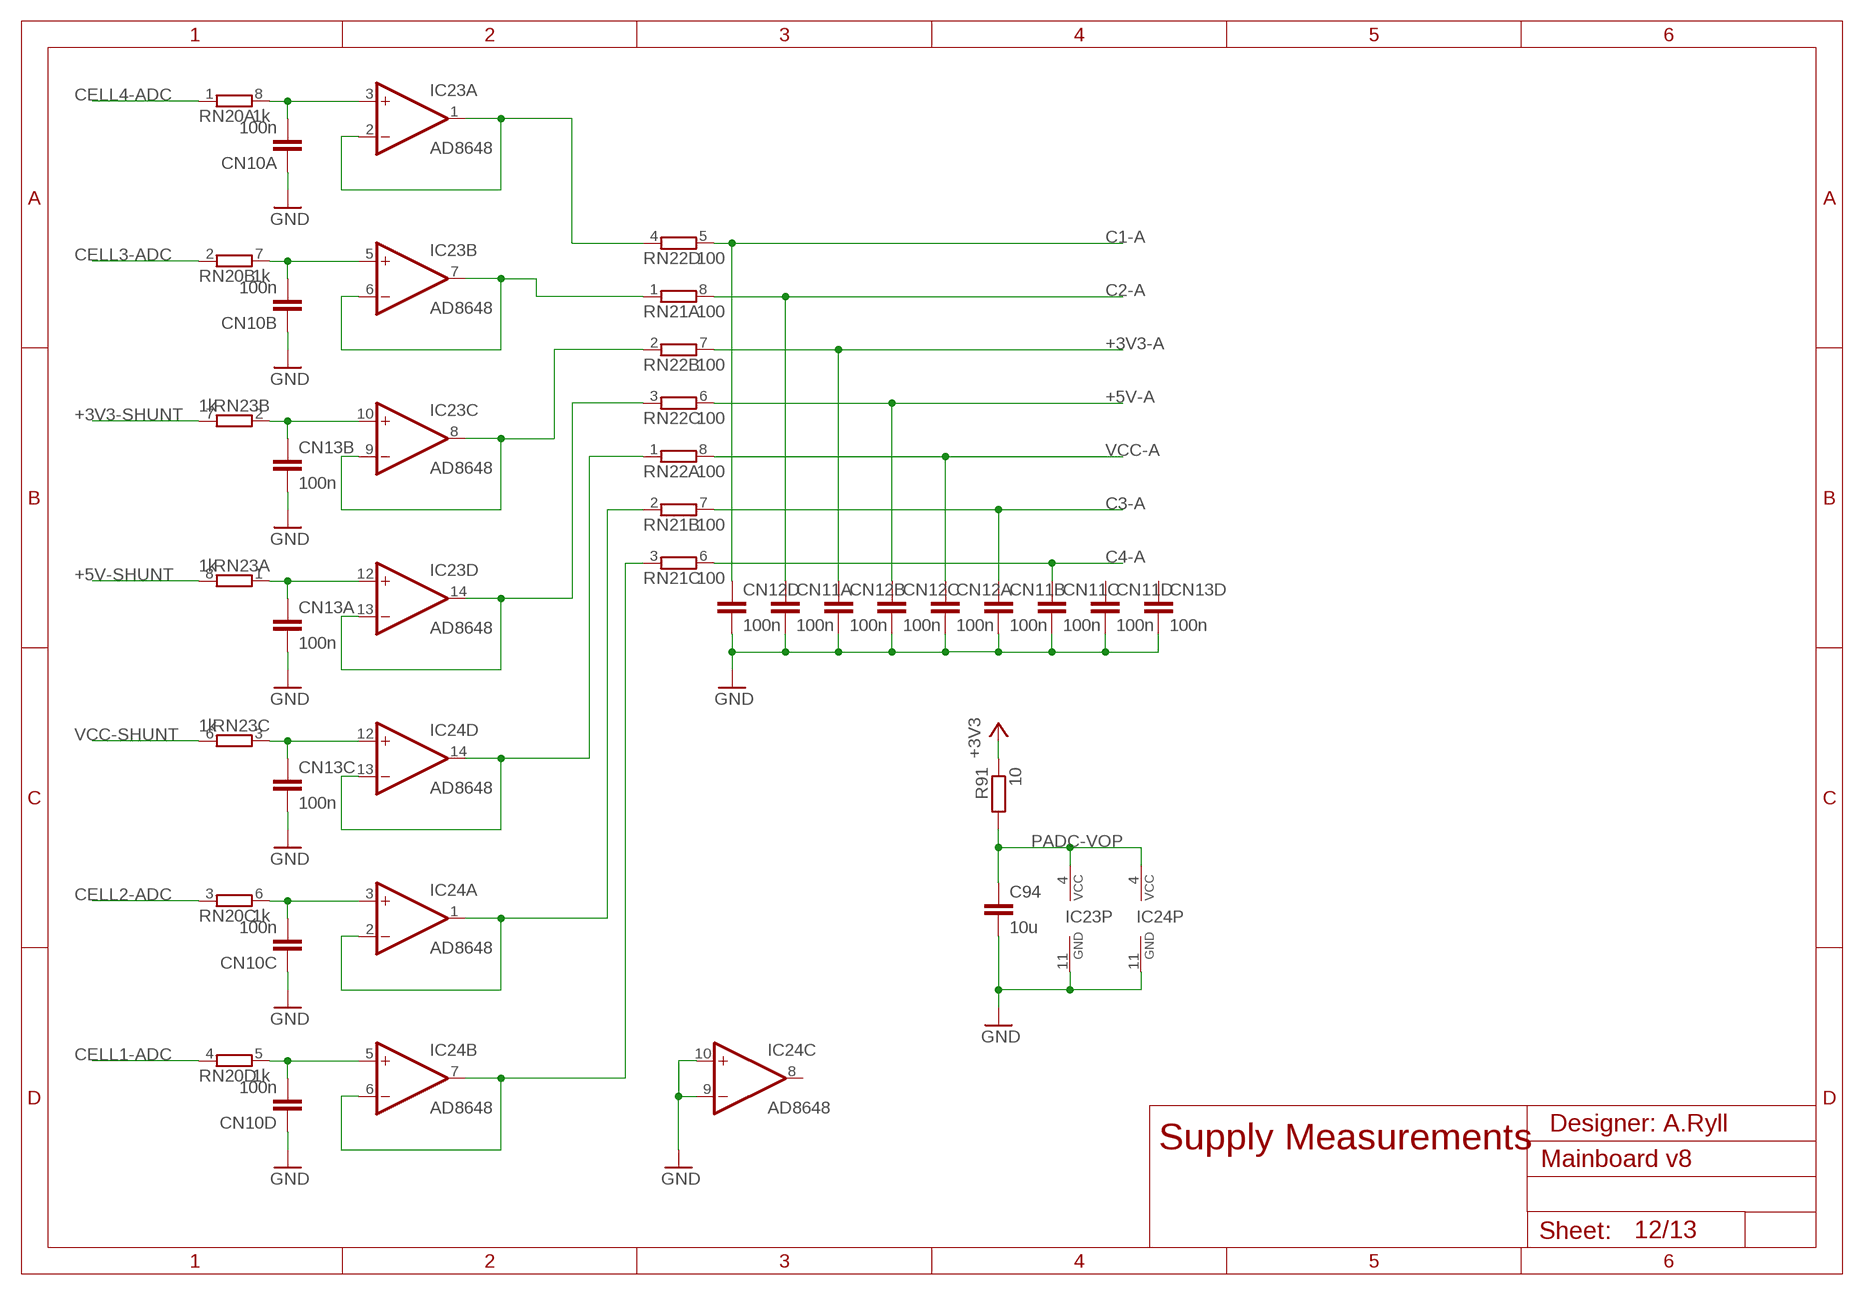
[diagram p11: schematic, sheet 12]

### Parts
C94  10u  C-EUC0805  [C0805]
CN10  100n  4C-NCAY16  [CAY16]
CN11  100n  4C-NCAY16  [CAY16]
CN12  100n  4C-NCAY16  [CAY16]
CN13  100n  4C-NCAY16  [CAY16]
IC23  AD8648  AD-OP4  [TSSOP14]
IC24  AD8648  AD-OP4  [TSSOP14]
R91  10  R-EU_R0805  [R0805]
RN20  1k  4R-NCAY16  [CAY16]
RN21  100  4R-NCAY16  [CAY16]
RN22  100  4R-NCAY16  [CAY16]
RN23  1k  4R-NCAY16  [CAY16]

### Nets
+3V3: R91.1 ; also sheet 1,2,3,4,5,6,7,8,9,11,13
+3V3-A: CN12.2 RN22.7 ; also sheet 13
+3V3-SHUNT: RN23.7 ; also sheet 11
+5V-A: CN12.3 RN22.6 ; also sheet 13
+5V-SHUNT: RN23.8 ; also sheet 11
C1-A: CN12.4 RN22.5 ; also sheet 13
C2-A: CN11.1 RN21.8 ; also sheet 13
C3-A: CN11.2 RN21.7 ; also sheet 13
C4-A: CN11.3 RN21.6 ; also sheet 13
CELL1-ADC: RN20.4 ; also sheet 10
CELL2-ADC: RN20.3 ; also sheet 10
CELL3-ADC: RN20.2 ; also sheet 10
CELL4-ADC: RN20.1 ; also sheet 10
GND: C94.2 CN10.1 CN10.2 CN10.3 CN10.4 CN11.5 CN11.6 CN11.7 CN11.8 CN12.5 CN12.6 CN12.7 CN12.8 CN13.5 CN13.6 CN13.7 CN13.8 IC23.11(P:GND) IC24.9(C:-IN) IC24.10(C:+IN) IC24.11(P:GND) ; also sheet 1,2,3,4,5,6,7,8,9,10,11,13
N$78: CN10.8 IC23.3(A:+IN) RN20.8
N$84: CN13.3 IC24.12(D:+IN) RN23.3
N$85: IC24.13(D:-IN) IC24.14(D:OUT) RN22.1
N$87: CN10.6 IC24.3(A:+IN) RN20.6
N$88: IC24.1(A:OUT) IC24.2(A:-IN) RN21.2
N$90: CN10.5 IC24.5(B:+IN) RN20.5
N$91: IC24.6(B:-IN) IC24.7(B:OUT) RN21.3
N$116: IC23.1(A:OUT) IC23.2(A:-IN) RN22.4
N$118: CN10.7 IC23.5(B:+IN) RN20.7
N$119: IC23.6(B:-IN) IC23.7(B:OUT) RN21.1
N$122: CN13.2 IC23.10(C:+IN) RN23.2
N$123: IC23.8(C:OUT) IC23.9(C:-IN) RN22.2
N$125: CN13.1 IC23.12(D:+IN) RN23.1
N$126: IC23.13(D:-IN) IC23.14(D:OUT) RN22.3
PADC-VOP: C94.1 IC23.4(P:VCC) IC24.4(P:VCC) R91.2
VCC-A: CN12.1 RN22.8 ; also sheet 13
VCC-SHUNT: RN23.6 ; also sheet 10
Unconnected: CN11.4 CN13.4 IC24.8(C:OUT) RN21.4 RN21.5 RN23.4 RN23.5

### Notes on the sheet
- Designer: A.Ryll
- Supply Measurements

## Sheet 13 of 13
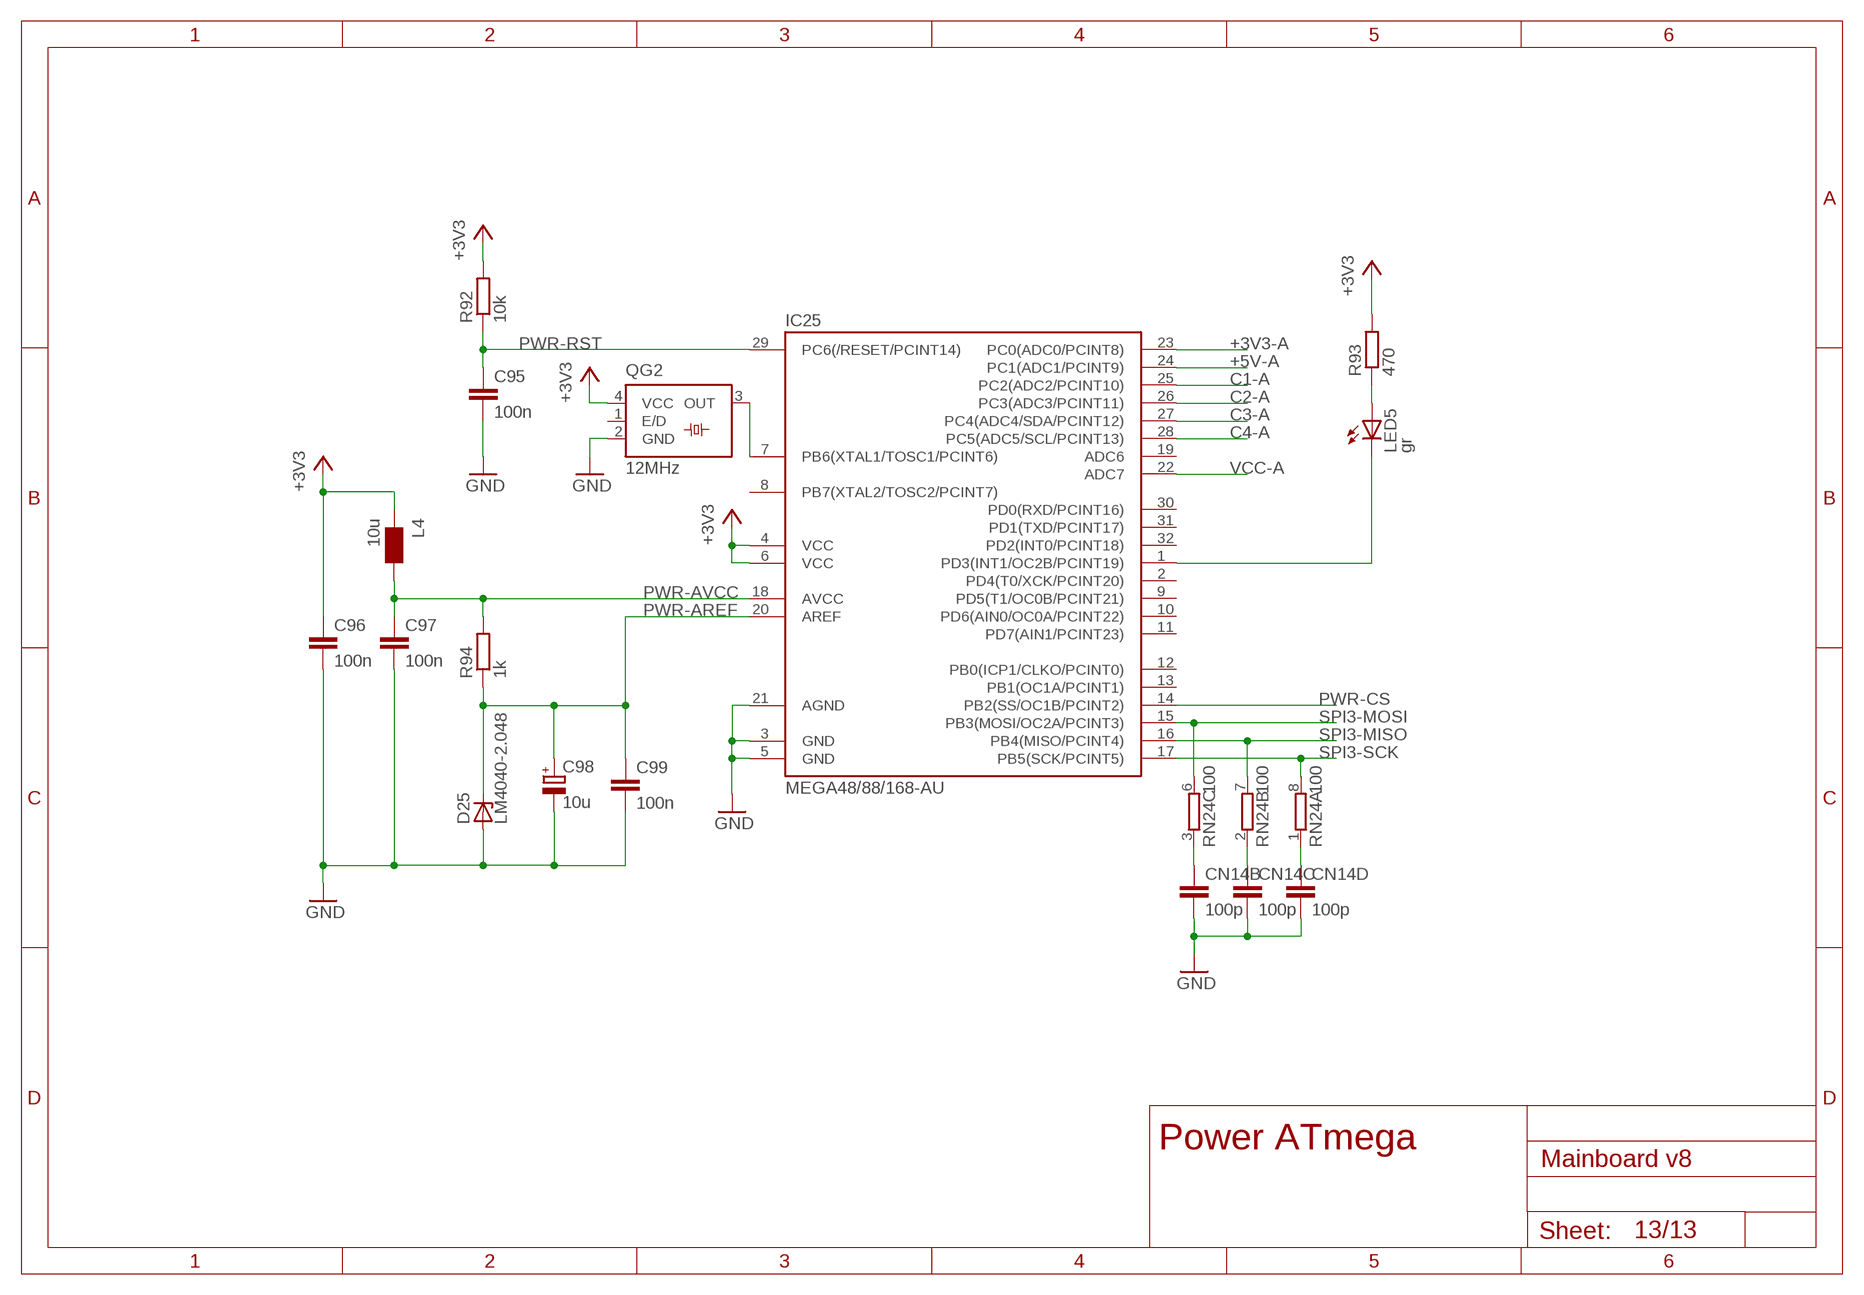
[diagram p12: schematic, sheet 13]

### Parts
C95  100n  C-EUC0805  [C0805]
C96  100n  C-EUC0805  [C0805]
C97  100n  C-EUC0805  [C0805]
C98  10u  CPOL-EUC/6032-28W  [C/6032-28W]
C99  100n  C-EUC0805  [C0805]
CN14  100p  4C-NCAY16  [CAY16]
D25  LM4040-2.048  ZENER-DIODELM4040  [SOT23]
IC25  MEGA48/88/168-AU  [TQFP32-08]
L4  10u  WE-MI_0805  [0805]
LED5  gr  LEDCHIP-LED0805  [CHIP-LED0805]
QG2  12MHz  SM77H  [SM77H]
R92  10k  R-EU_R0805  [R0805]
R93  470  R-EU_R0805  [R0805]
R94  1k  R-EU_R0805  [R0805]
RN24  100  4R-NCAY16  [CAY16]

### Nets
+3V3: C96.1 IC25.4(VCC) IC25.6(VCC) L4.1 QG2.4(VCC) R92.2 R93.2 ; also sheet 1,2,3,4,5,6,7,8,9,11,12
+3V3-A: IC25.23(PC0(ADC0/PCINT8)) ; also sheet 12
+5V-A: IC25.24(PC1(ADC1/PCINT9)) ; also sheet 12
C1-A: IC25.25(PC2(ADC2/PCINT10)) ; also sheet 12
C2-A: IC25.26(PC3(ADC3/PCINT11)) ; also sheet 12
C3-A: IC25.27(PC4(ADC4/SDA/PCINT12)) ; also sheet 12
C4-A: IC25.28(PC5(ADC5/SCL/PCINT13)) ; also sheet 12
GND: C95.2 C96.2 C97.2 C98.- C99.2 CN14.5 CN14.6 CN14.7 D25.2(A) IC25.3(GND) IC25.5(GND) IC25.21(AGND) QG2.2(GND) ; also sheet 1,2,3,4,5,6,7,8,9,10,11,12
N$32: LED5.A R93.1
N$153: IC25.1(PD3(INT1/OC2B/PCINT19)) LED5.C
N$167: CN14.2 RN24.3
N$170: CN14.3 RN24.2
N$172: CN14.4 RN24.1
PWR-AREF: C98.+ C99.1 D25.1(C) IC25.20(AREF) R94.1
PWR-AVCC: C97.1 IC25.18(AVCC) L4.2 R94.2
PWR-CS: IC25.14(PB2(SS/OC1B/PCINT2)) ; also sheet 9
PWR-RST: C95.1 IC25.29(PC6(/RESET/PCINT14)) R92.1 ; also sheet 9
PWR-XTAL: IC25.7(PB6(XTAL1/TOSC1/PCINT6)) QG2.3(OUT)
SPI3-MISO: IC25.16(PB4(MISO/PCINT4)) RN24.7 ; also sheet 6,7,9
SPI3-MOSI: IC25.15(PB3(MOSI/OC2A/PCINT3)) RN24.6 ; also sheet 6,7,9
SPI3-SCK: IC25.17(PB5(SCK/PCINT5)) RN24.8 ; also sheet 6,7,9
VCC-A: IC25.22(ADC7) ; also sheet 12
Unconnected: CN14.1 CN14.8 IC25.2(PD4(T0/XCK/PCINT20)) IC25.8(PB7(XTAL2/TOSC2/PCINT7)) IC25.9(PD5(T1/OC0B/PCINT21)) IC25.10(PD6(AIN0/OC0A/PCINT22)) IC25.11(PD7(AIN1/PCINT23)) IC25.12(PB0(ICP1/CLKO/PCINT0)) IC25.13(PB1(OC1A/PCINT1)) IC25.19(ADC6) IC25.30(PD0(RXD/PCINT16)) IC25.31(PD1(TXD/PCINT17)) IC25.32(PD2(INT0/PCINT18)) QG2.1(E/D) RN24.4 RN24.5

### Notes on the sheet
- Power ATmega

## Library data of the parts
BAT1# BAT1+ BAT1- BAT2# BAT2+ BAT2- = Marvin:WIREPAD: Wire PAD connect wire on PCB
BD ENC1-ENC4 KDPWR = con-molex:22-?-04: CONNECTOR wire to board 2.54 mm (.1 inch) pitch header; OC_FARNELL: unknown; OC_NEWARK: unknown
BUZZ = buzzer:F/CM12P: BUZZER
C1 C3-C8 C11-C16 C19-C24 C27-C32 C35-C44 C46-C53 C55-C58 C60-C75 C77-C97 C99-C101 = rcl:C-EU: CAPACITOR, European symbol
C2 C10 C18 C26 C34 = Marvin:CPOL-EU
C45 C54 C59 C76 C98 = rcl:CPOL-EU: POLARIZED CAPACITOR, European symbol
CN1-CN5 CN7 CN8 CN10-CN14 = Marvin:4C-N: Array Chip Capacitor; OC_FARNELL: unknown; OC_NEWARK: unknown
D1-D3 D5-D7 D9-D11 D13-D15 D17-D19 = diode:DIODE-: DIODE
D21 D25 = Marvin:ZENER-DIODE: Z-Diode
D22-D24 = diode:SCHOTTKY-DIODE: Schottky Diode
EXT = con-samtec:SSW-110-02-S-D: THROUGH-HOLE .025" SQ POST SOCKET Source: Samtec SSW.pdf; MPN: SSW-110-02-S-D; OC_FARNELL: unknown; OC_NEWARK: 11P9480
EXTPWR = con-samtec:SSW-102-02-S-D: THROUGH-HOLE .025" SQ POST SOCKET Source: Samtec SSW.pdf; MPN: SSW-102-02-S-D; OC_FARNELL: unknown; OC_NEWARK: 11P9349
F1 = Marvin:FUSE5X20: 1 SCHURTER 0031.3558
FLT1-FLT5 LED1-LED5 RX TX = led:LED: LED
IC1-IC5 = Marvin:IR2130
IC6 IC7 IC26-IC28 = Marvin:MAX4372
IC8 IC25 = avr-6:MEGA48/88/168
IC9 = Marvin:AD-OP1
IC10-IC12 = Marvin:74*86: Quad 2-input EXCLUSIVE-OR (XOR) gate
IC13 = Marvin:L3G4200D
IC14 = Marvin:LIS3DH
IC15 = ftdichip:FT232R: Source: http://www.ftdichip.com/Documents/DataSheets/DS_FT232R_v104.pdf; MPN: FT232RL; OC_FARNELL: 1146032; OC_NEWARK: 91K9918
IC16 = Marvin:STM32F40_Z: 168 MHz, 192KB RAM, 1024 KB Flash
IC17 IC20 IC22 = burr-brown:INA138: High-Side Measurement Current Shunt Monitor
IC18 = Marvin:LT1910
IC19 IC21 = Marvin:LT3480
IC23 IC24 = Marvin:AD-OP4
JTAG = con-harting-ml:ML20: HARTING
KD = con-harting-ml:ML10: HARTING
L1 L4 = wuerth-elektronik:WE-MI: SMD Multilayer Inductor WE-MI
L2 L3 = Marvin:L
M1-M4 = Marvin:MOLEX11
M5 = con-molex:22-?-08: CONNECTOR wire to board 2.54 mm (.1 inch) pitch header; OC_FARNELL: unknown; OC_NEWARK: unknown
Q1-Q30 = Marvin:NMOS4D
Q31 Q32 Q35 = transistor-npn:BCW60*: NPN Transistor
Q33 = Marvin:CRYSTAL
Q34 = Marvin:NMOS
Q36-Q40 = transistor-small-signal:BSS123: N-CHANNEL MOS FET
QG1 QG2 = Marvin:SM77H: 3.3V CMOS Clock Oscillator Source: www.pletronics.com .. sm77h%203.3v.pdf
R1 R6 R7 R12 R13 R18 R19 R24 R25 R30 R43-R94 = rcl:R-EU_: RESISTOR, European symbol
RESET = Marvin:BUTTON4: Tyco Push Button FSM2JSMA Farnell Order: 3801287
RN1-RN10 RN12 RN13 RN15-RN24 = resistor-dil:4R-N: Array Chip Resistor Source: RS Component / Phycomp; OC_FARNELL: unknown; OC_NEWARK: unknown
SJ1 SJ2 = jumper:SJ: SMD solder JUMPER
SW1 = Marvin:SPDT: Tyco Number: AE101J1AQ404
USB1 = Marvin:USB-BMINI
WF1 = Marvin:NRFL01MOD

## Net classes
0 default: width 0.152 mm, clearance 0.152 mm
